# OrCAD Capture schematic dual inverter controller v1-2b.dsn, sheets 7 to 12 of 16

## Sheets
7 Current Sensor XYZ: size B; title: Controller
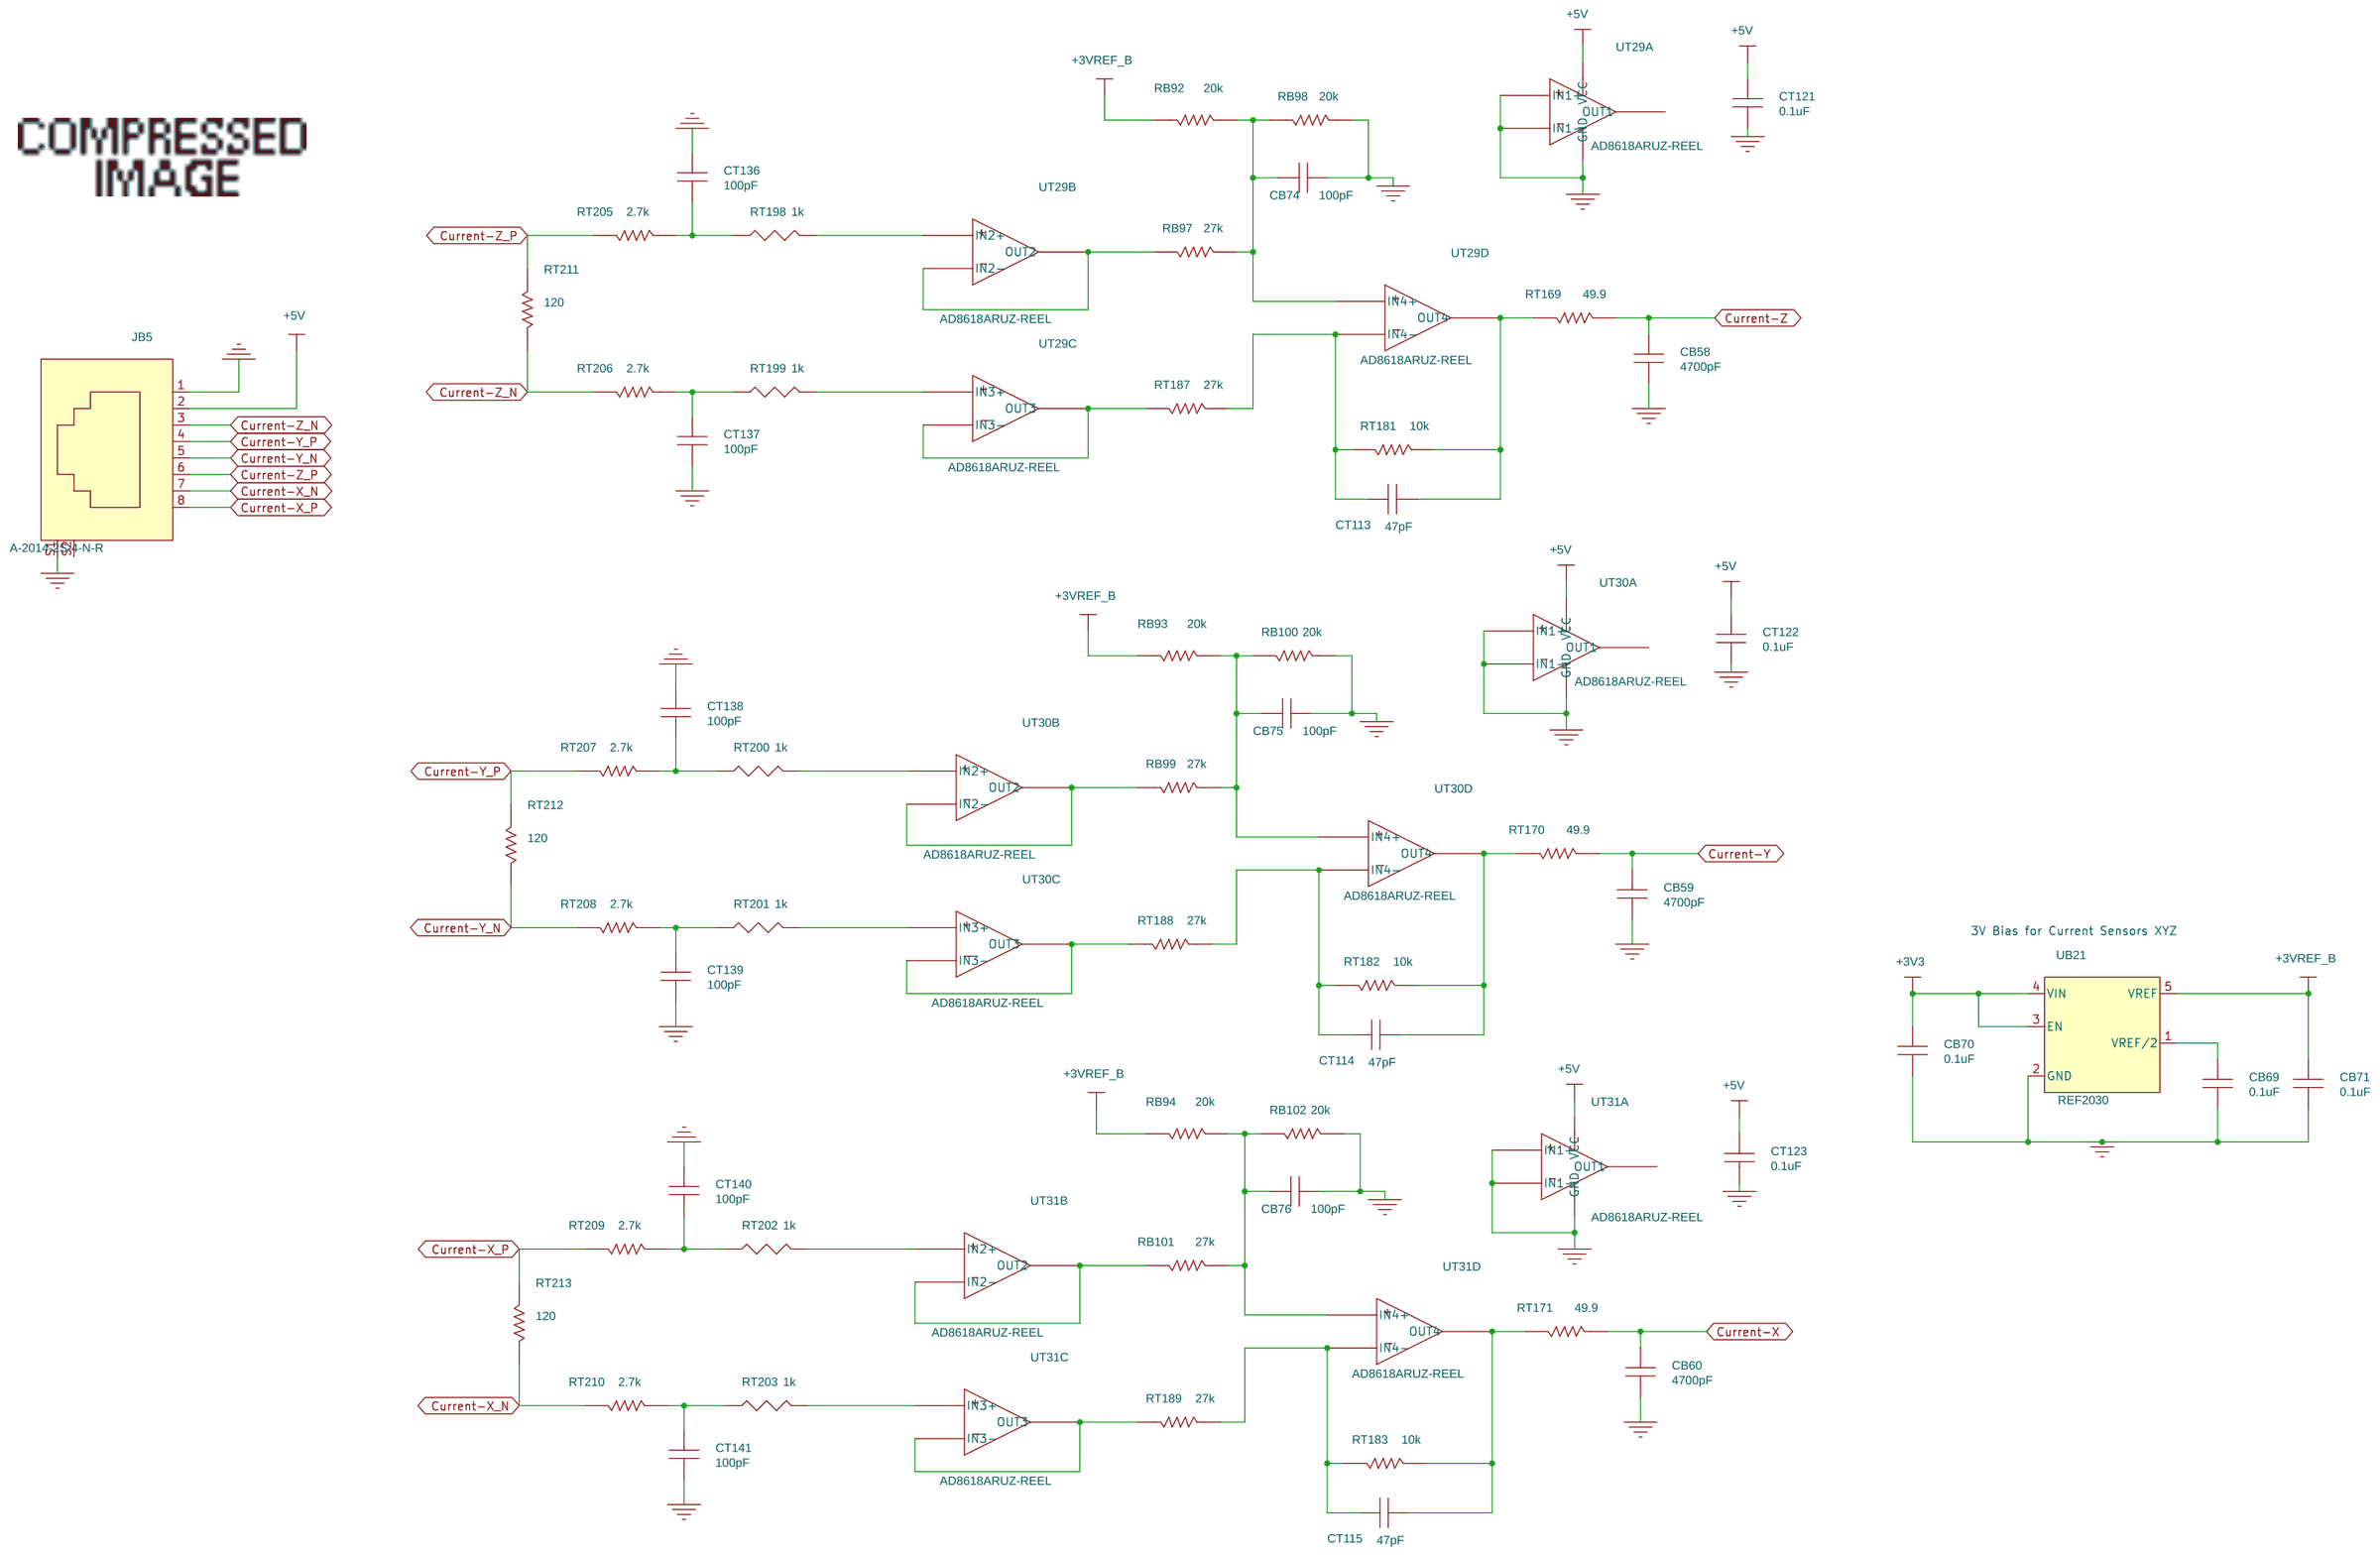
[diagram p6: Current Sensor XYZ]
8 Gate Driver Interface UVW: size A; title: Controller
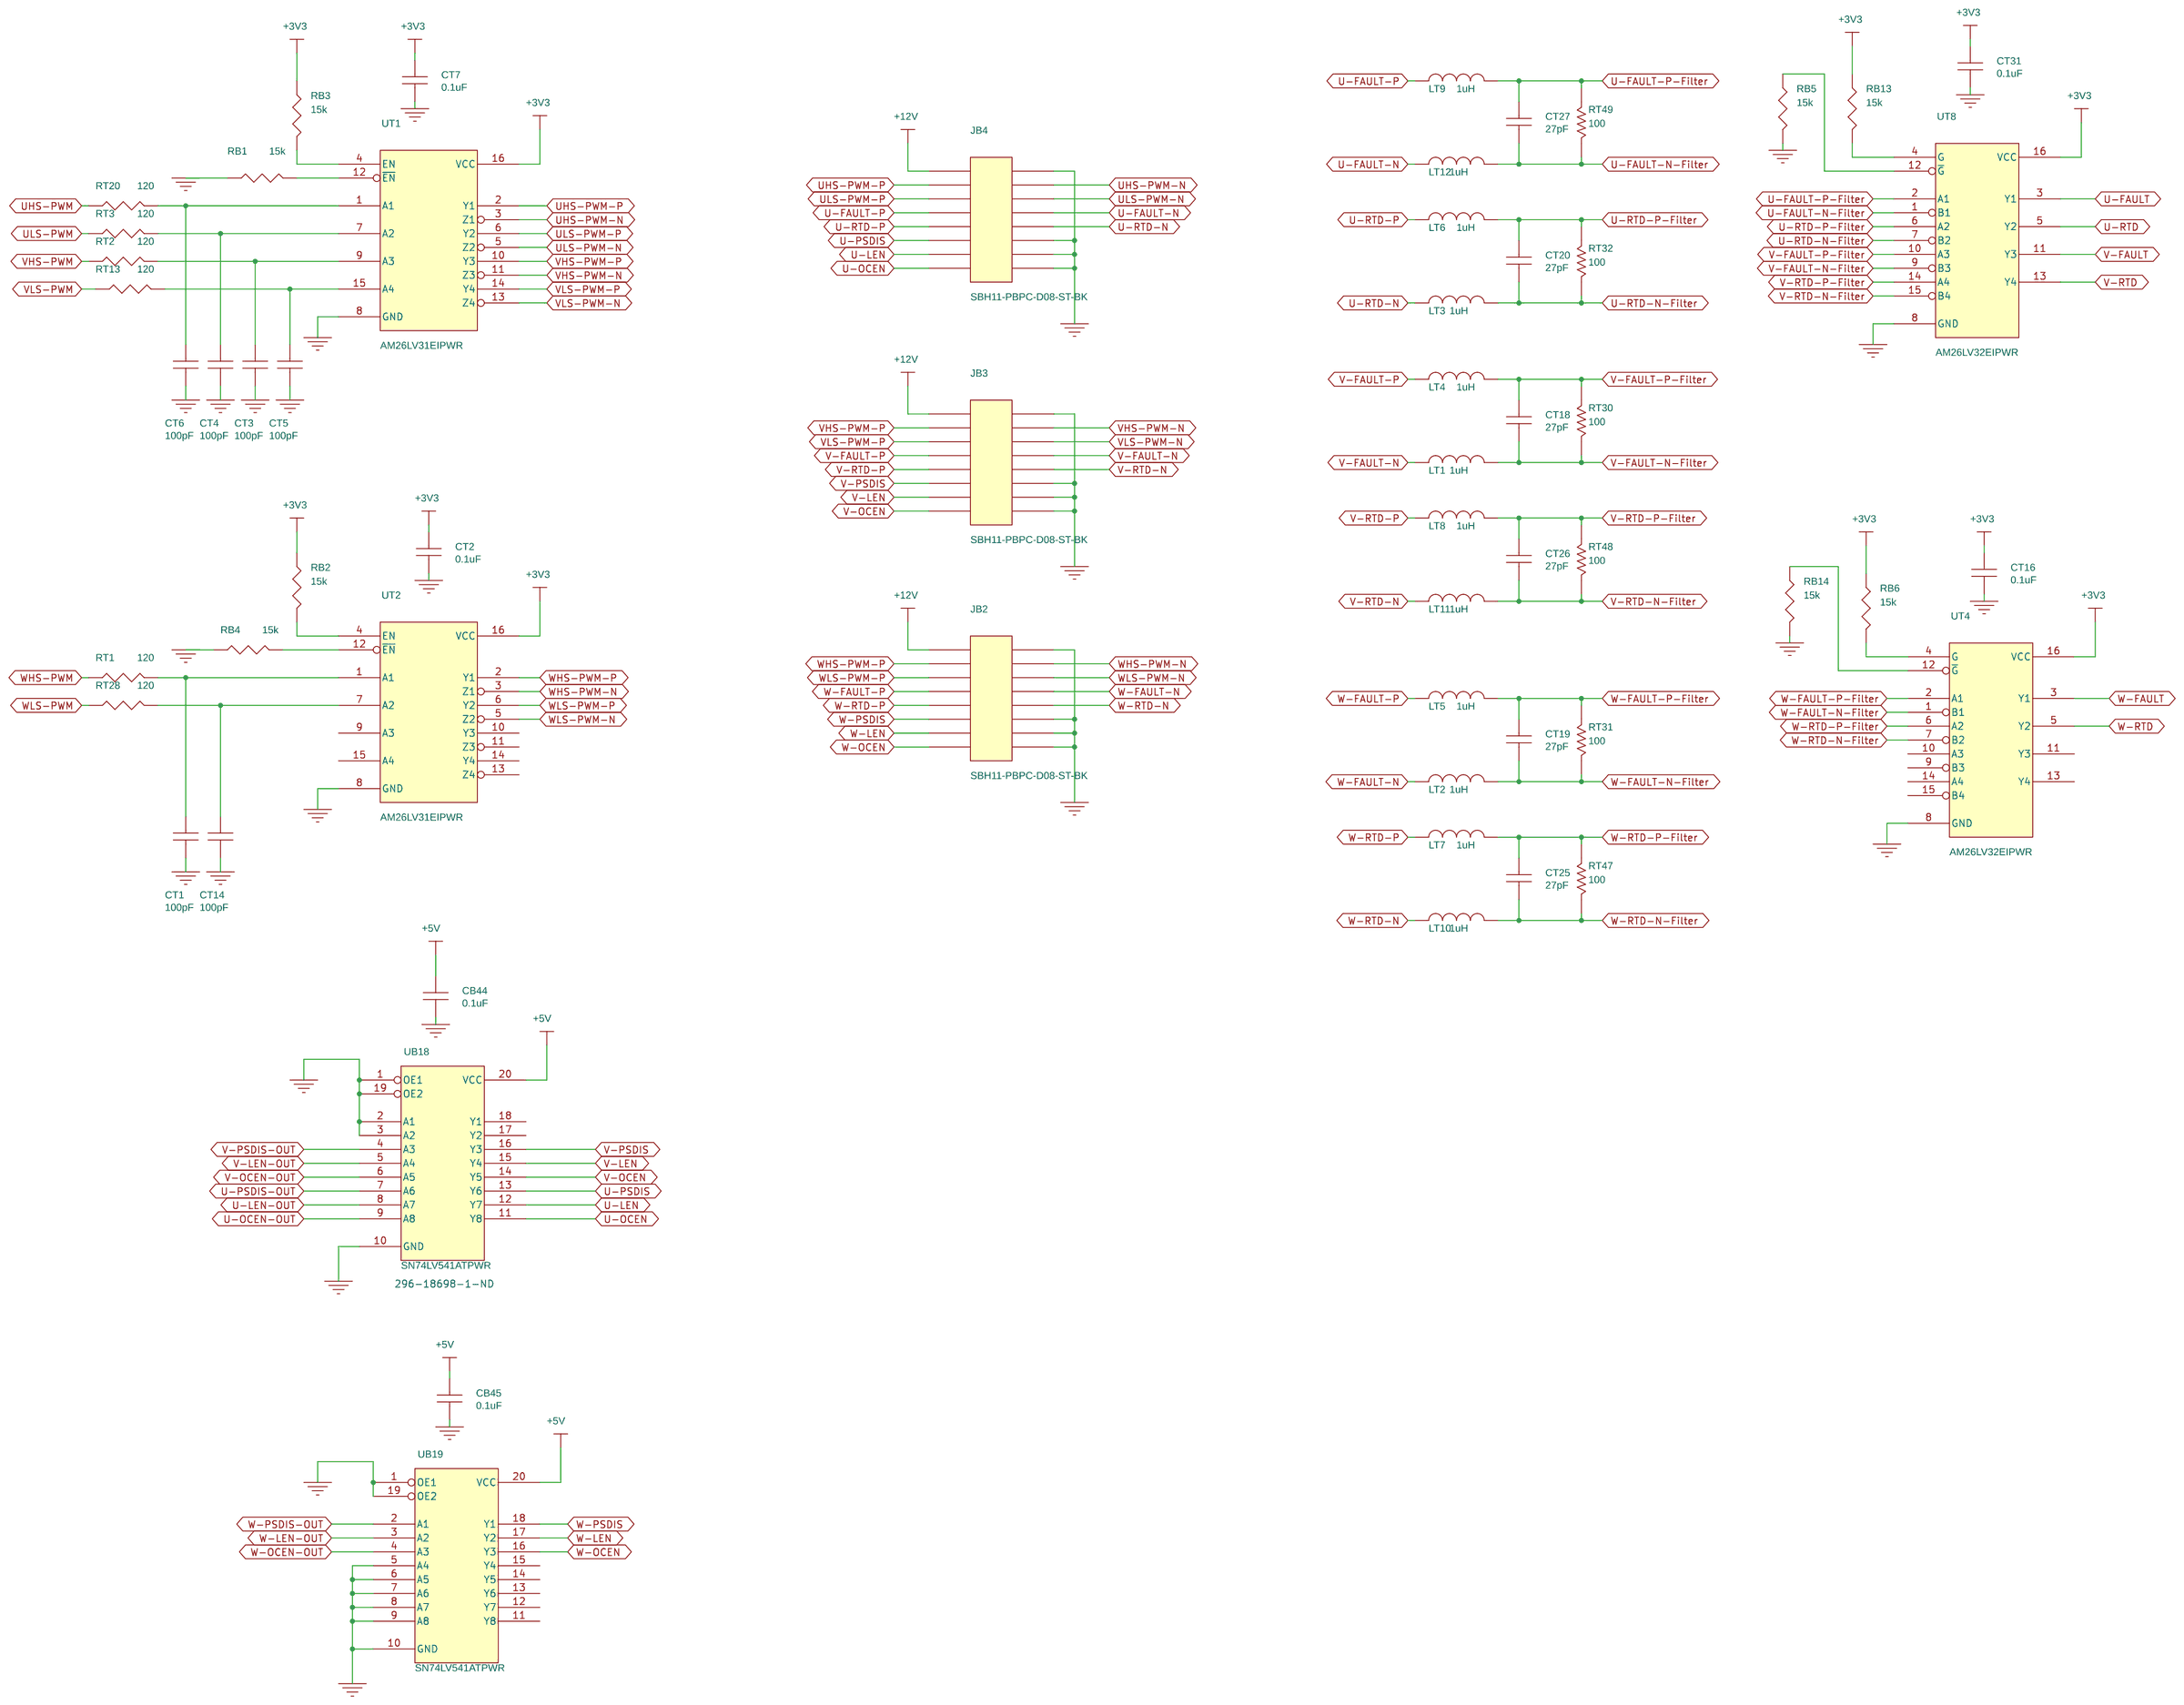
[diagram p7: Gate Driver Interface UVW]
9 Gate Driver Interfave XYZ: size A; title: Controller
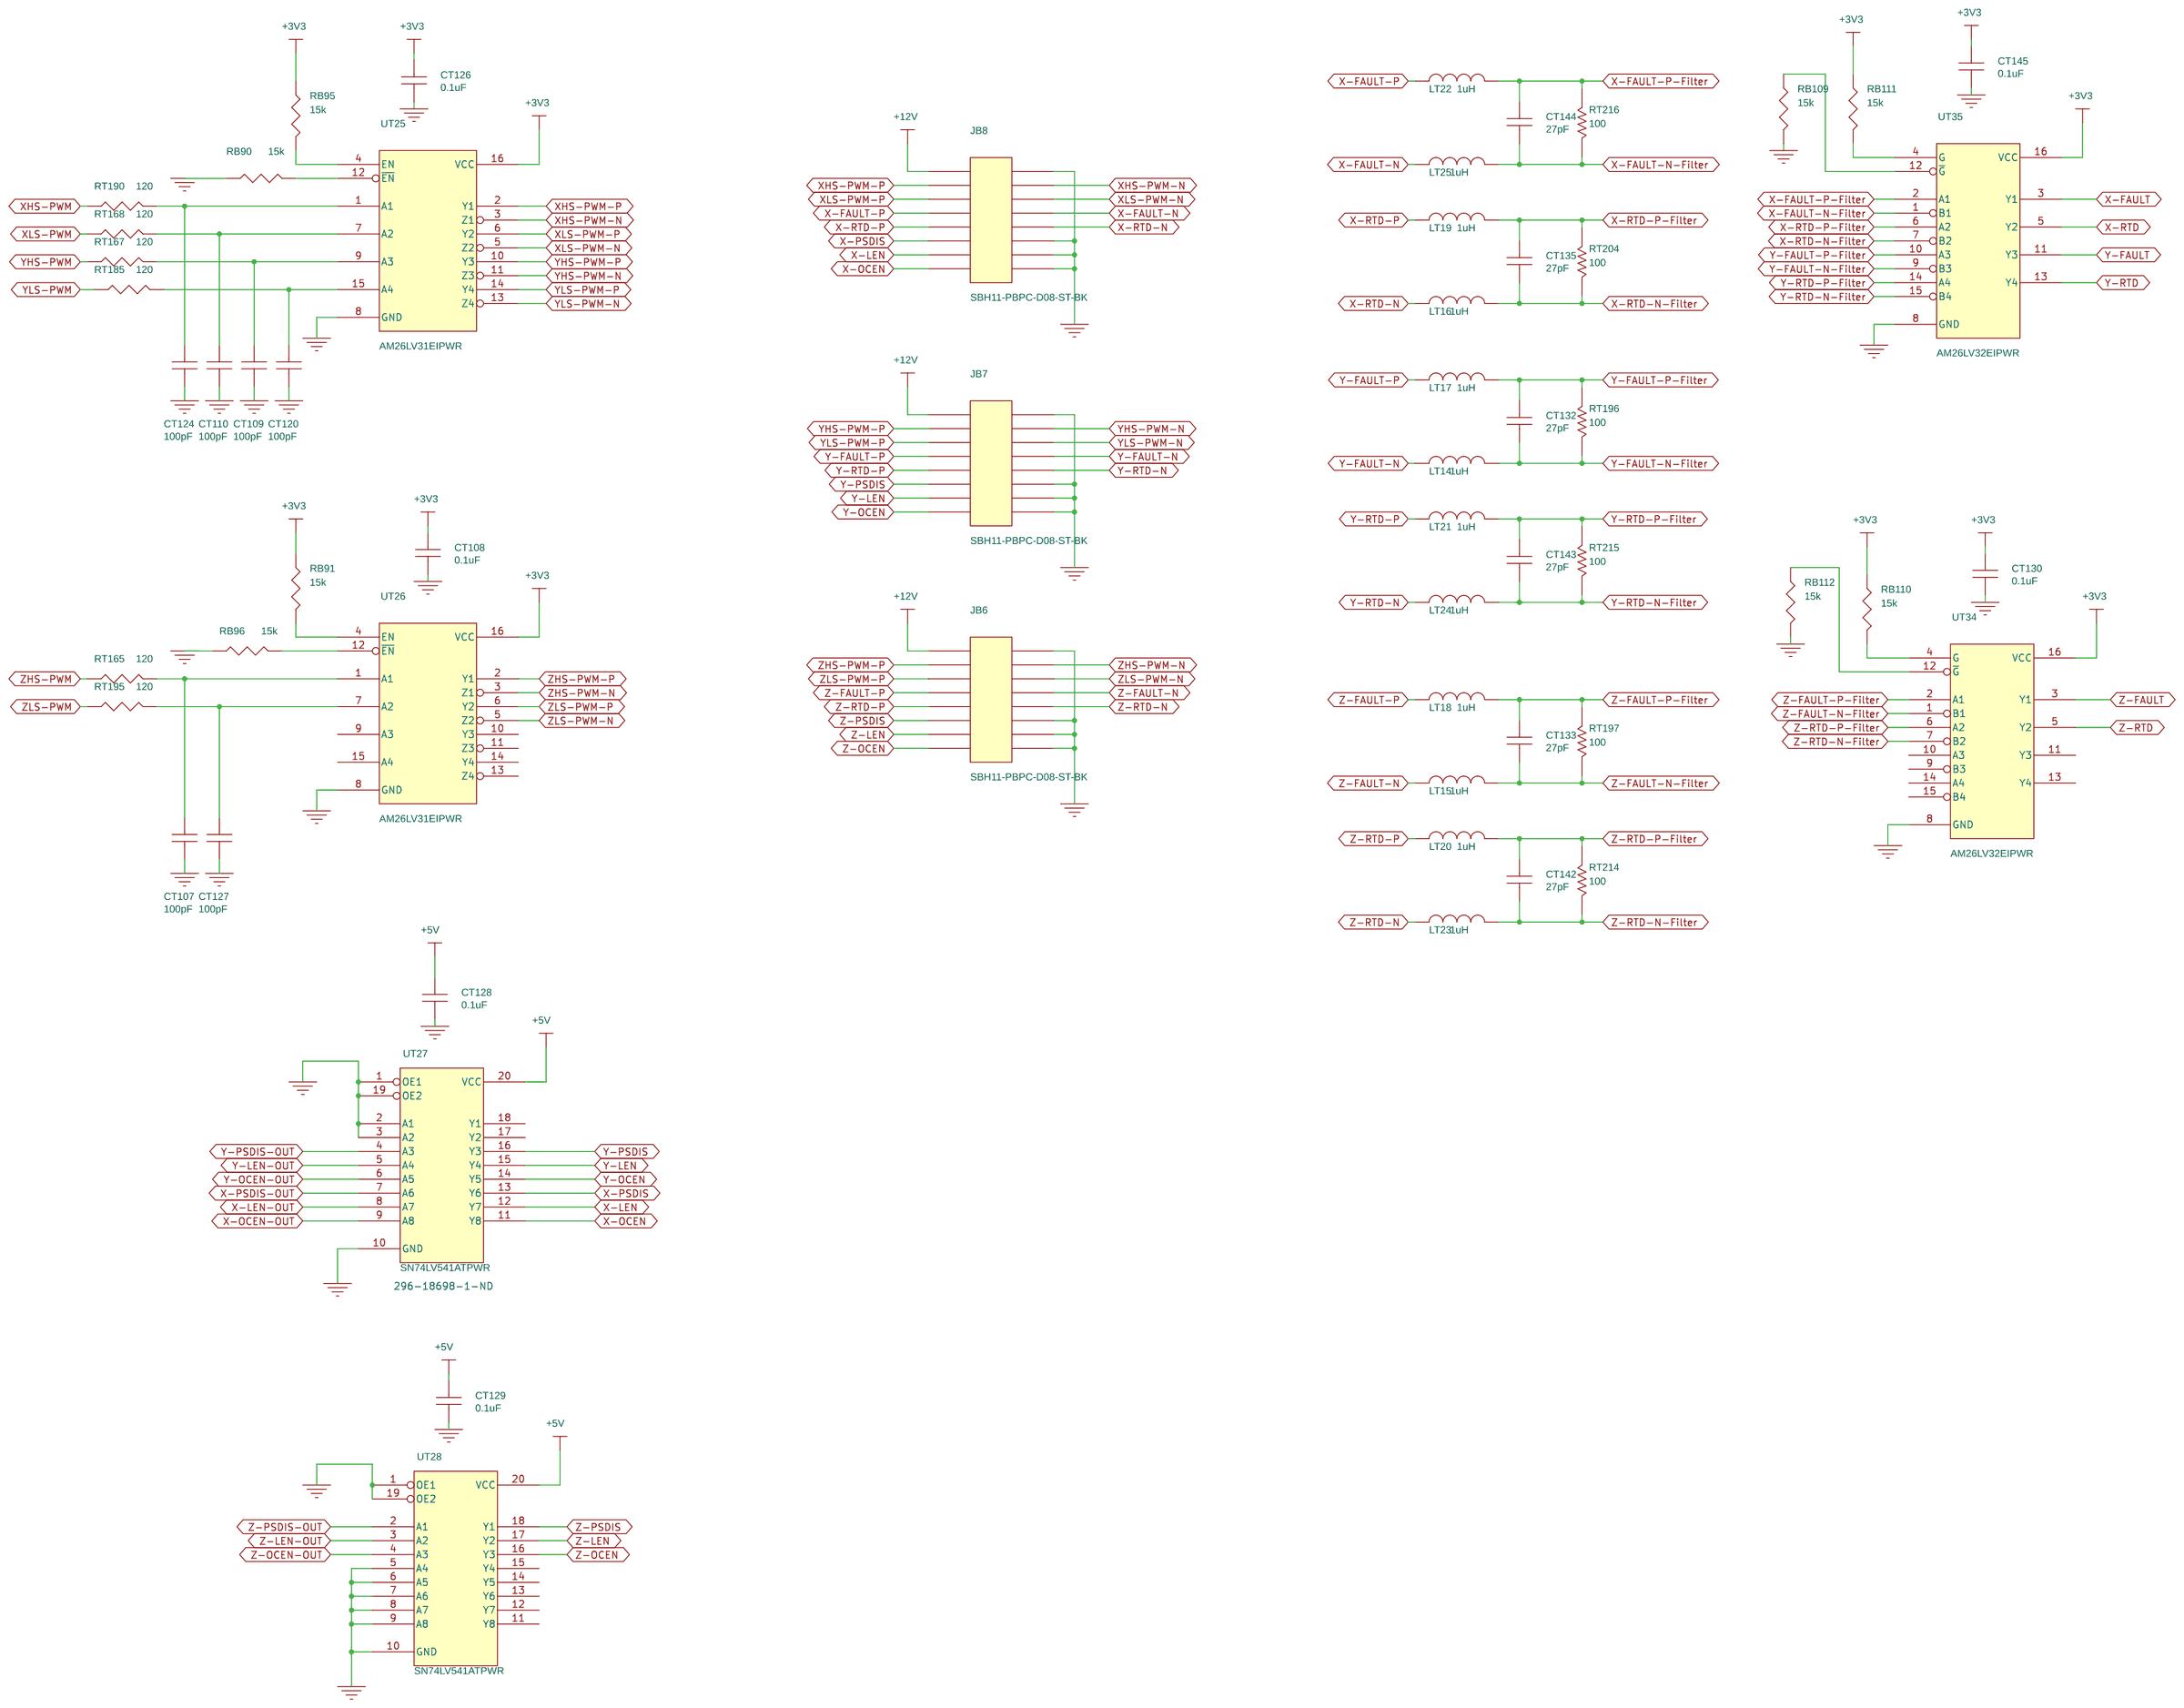
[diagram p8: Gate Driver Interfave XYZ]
10 Power Supply: size A; title: Controller
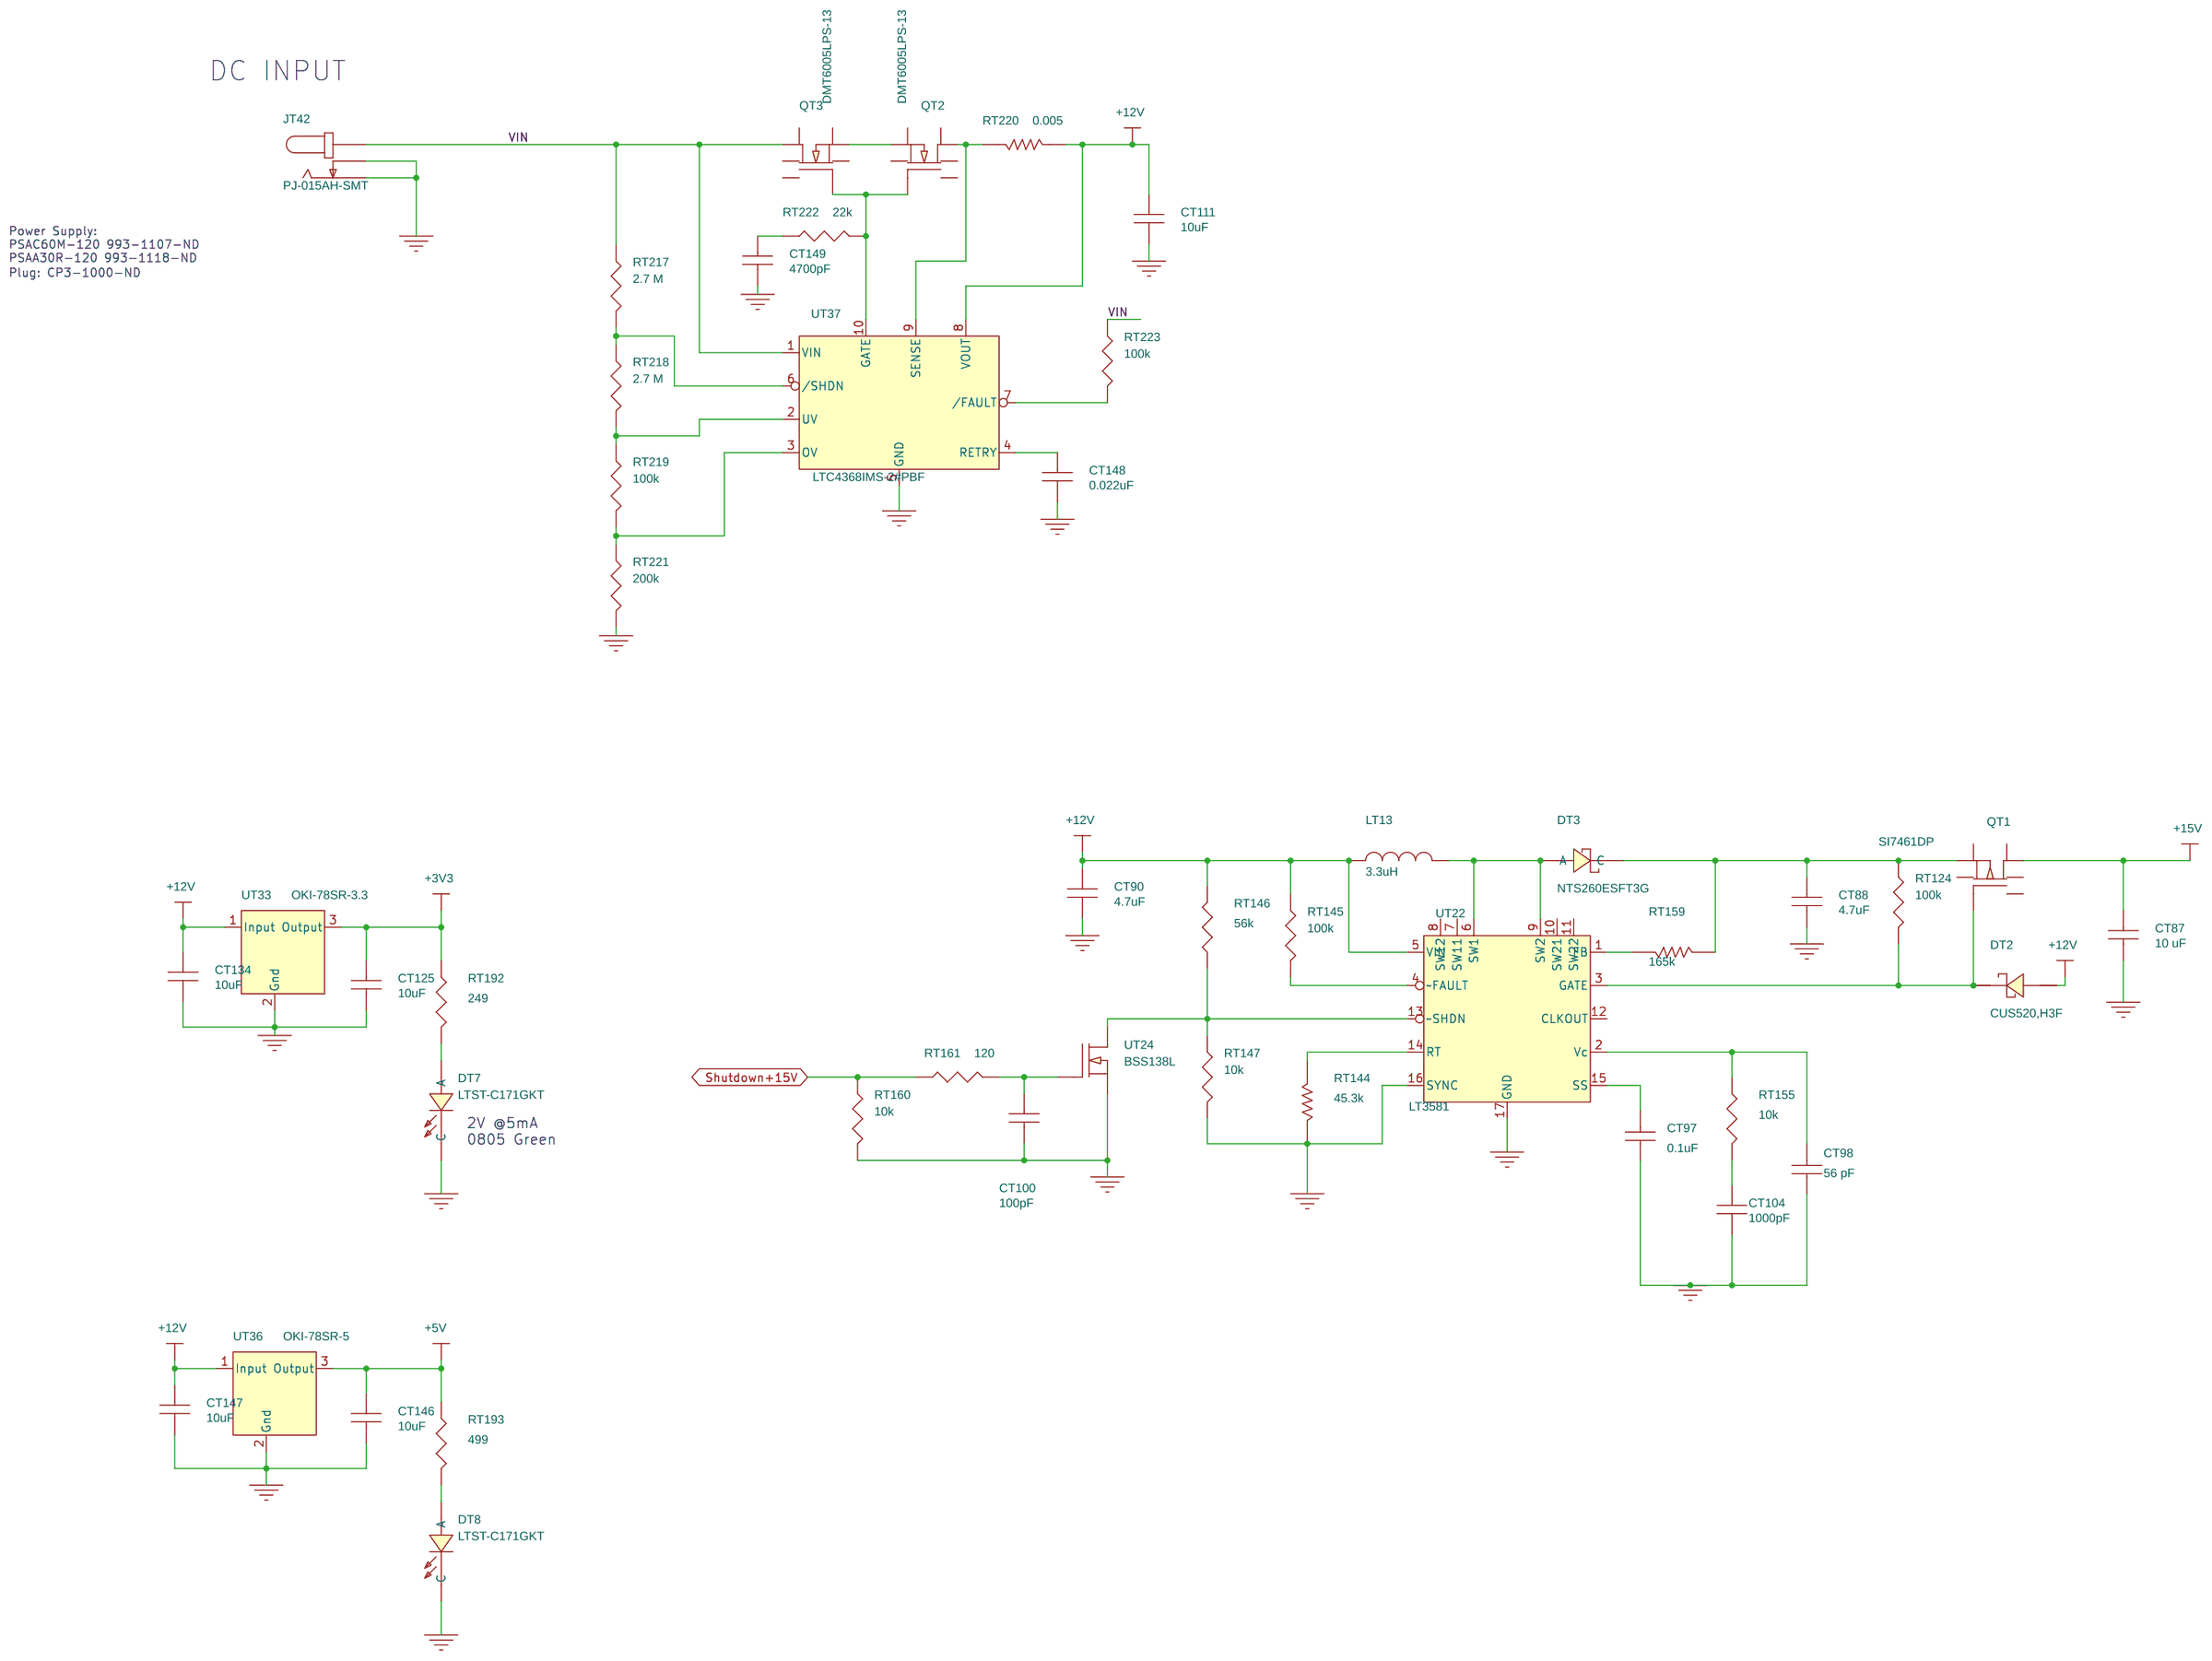
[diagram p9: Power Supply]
11 QEP: size A; title: Controller
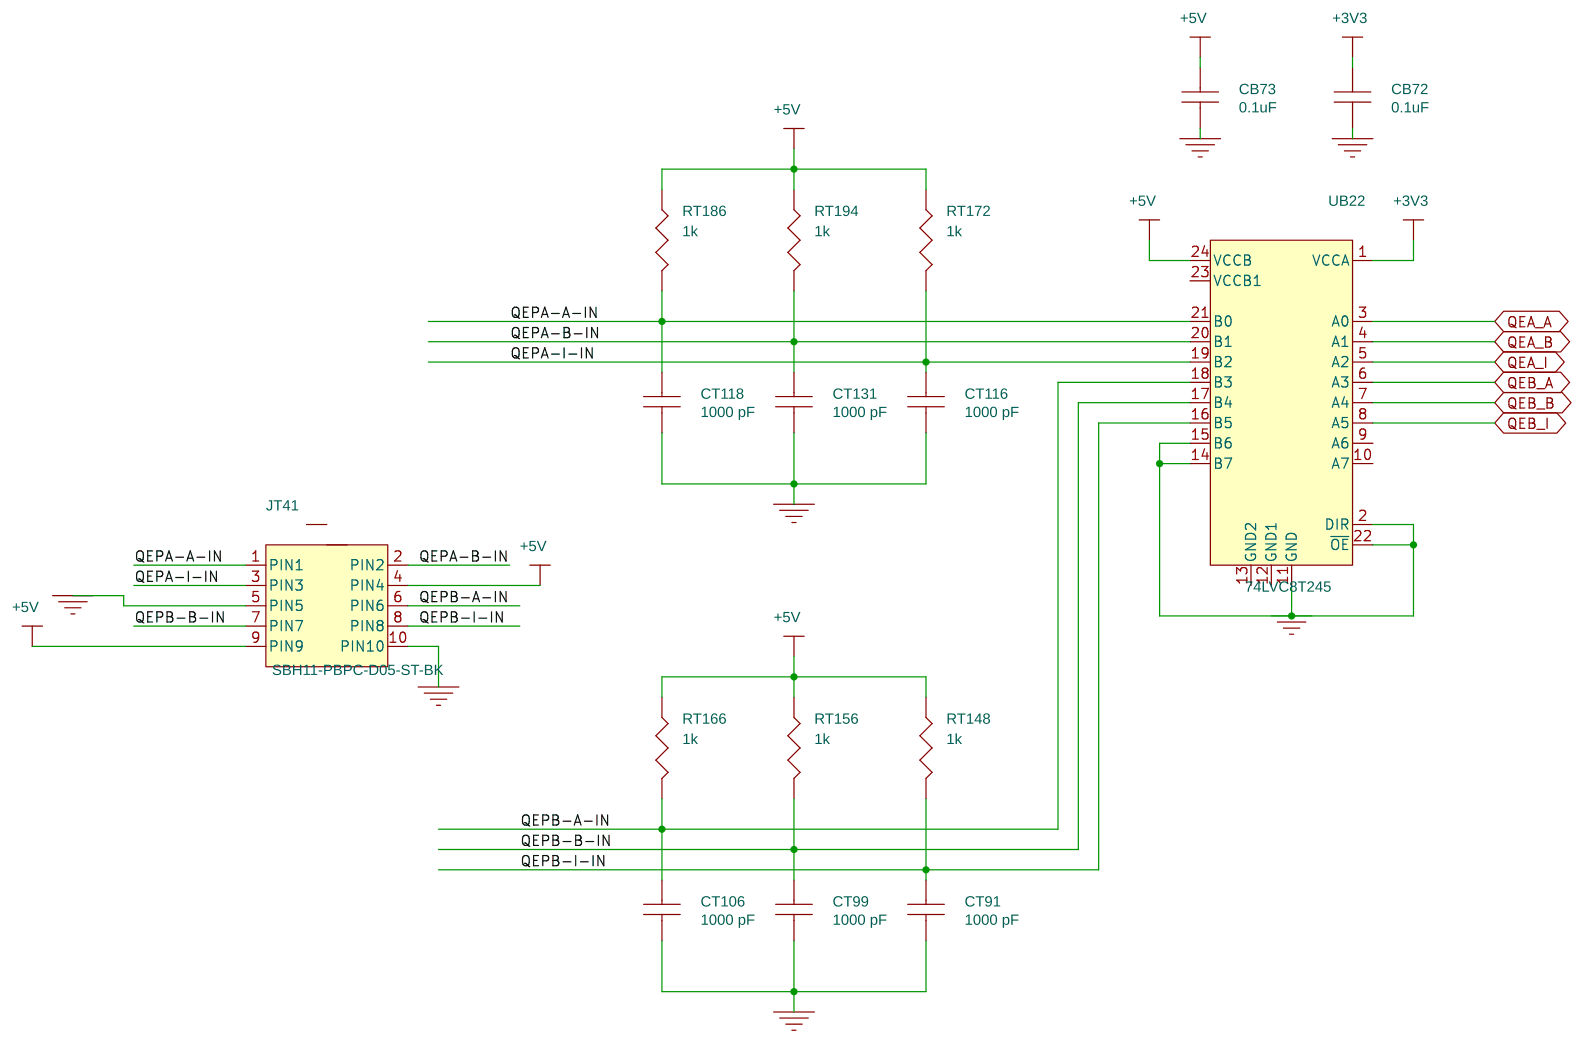
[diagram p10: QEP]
12 Revision History: title: Controller
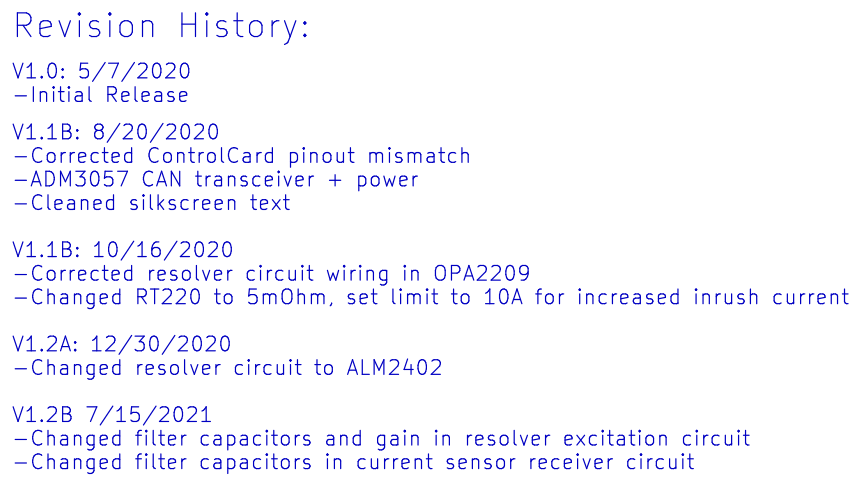
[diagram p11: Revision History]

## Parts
sheet Current Sensor XYZ
CB58  4700pF  [c_0603]
CB59  4700pF  [c_0603]
CB60  4700pF  [c_0603]
CB69  0.1uF  [CAPC1608X87N]
CB70  0.1uF  [CAPC1608X87N]
CB71  0.1uF  [CAPC1608X87N]
CB74  100pF  [CAPC1608X90N]
CB75  100pF  [CAPC1608X90N]
CB76  100pF  [CAPC1608X90N]
CT113  47pF  [CAPC1608X87N]
CT114  47pF  [CAPC1608X87N]
CT115  47pF  [CAPC1608X87N]
CT121  0.1uF  [CAPC1608X87N]
CT122  0.1uF  [CAPC1608X87N]
CT123  0.1uF  [CAPC1608X87N]
CT136  100pF  [CAPC1608X90N]
CT137  100pF  [CAPC1608X90N]
CT138  100pF  [CAPC1608X90N]
CT139  100pF  [CAPC1608X90N]
CT140  100pF  [CAPC1608X90N]
CT141  100pF  [CAPC1608X90N]
JB5  A-2014-2S-4-N-R  [RJ45_VERT_SHIELD_CON]
RB92  20k  [RESC1608X55N]
RB93  20k  [RESC1608X55N]
RB94  20k  [RESC1608X55N]
RB97  27k  [RESC1608X55N]
RB98  20k  [RESC1608X55N]
RB99  27k  [RESC1608X55N]
RB100  20k  [RESC1608X55N]
RB101  27k  [RESC1608X55N]
RB102  20k  [RESC1608X55N]
RT169  49.9  [RESC1608X55N]
RT170  49.9  [RESC1608X55N]
RT171  49.9  [RESC1608X55N]
RT181  10k  [RESC1608X55N]
RT182  10k  [RESC1608X55N]
RT183  10k  [RESC1608X55N]
RT187  27k  [RESC1608X55N]
RT188  27k  [RESC1608X55N]
RT189  27k  [RESC1608X55N]
RT198  1k  [RESC1608X55N]
RT199  1k  [RESC1608X55N]
RT200  1k  [RESC1608X55N]
RT201  1k  [RESC1608X55N]
RT202  1k  [RESC1608X55N]
RT203  1k  [RESC1608X55N]
RT205  2.7k  [RESC1608X55N]
RT206  2.7k  [RESC1608X55N]
RT207  2.7k  [RESC1608X55N]
RT208  2.7k  [RESC1608X55N]
RT209  2.7k  [RESC1608X55N]
RT210  2.7k  [RESC1608X55N]
RT211  120  [RESC1608X55N]
RT212  120  [RESC1608X55N]
RT213  120  [RESC1608X55N]
UB21  REF2030  [SOT23-5_0_95X2_70P_H1_45]
UT29  AD8618ARUZ-REEL  [TSSOP-14]  (sections A,B,C,D)
UT30  AD8618ARUZ-REEL  [TSSOP-14]  (sections A,B,C,D)
UT31  AD8618ARUZ-REEL  [TSSOP-14]  (sections A,B,C,D)
sheet Gate Driver Interface UVW
CB44  0.1uF  [CAPC1608X87N]
CB45  0.1uF  [CAPC1608X87N]
CT1  100pF  [CAPC1608X90N]
CT2  0.1uF  [CAPC1608X87N]
CT3  100pF  [CAPC1608X90N]
CT4  100pF  [CAPC1608X90N]
CT5  100pF  [CAPC1608X90N]
CT6  100pF  [CAPC1608X90N]
CT7  0.1uF  [CAPC1608X87N]
CT14  100pF  [CAPC1608X90N]
CT16  0.1uF  [CAPC1608X87N]
CT18  27pF  [CAPC1608X90N]
CT19  27pF  [CAPC1608X90N]
CT20  27pF  [CAPC1608X90N]
CT25  27pF  [CAPC1608X90N]
CT26  27pF  [CAPC1608X90N]
CT27  27pF  [CAPC1608X90N]
CT31  0.1uF  [CAPC1608X87N]
JB2  SBH11-PBPC-D08-ST-BK  [CON_2x8_shrouded_corrected]
JB3  SBH11-PBPC-D08-ST-BK  [CON_2x8_shrouded_corrected]
JB4  SBH11-PBPC-D08-ST-BK  [CON_2x8_shrouded_corrected]
LT1  1uH  [l_0805]
LT2  1uH  [l_0805]
LT3  1uH  [l_0805]
LT4  1uH  [l_0805]
LT5  1uH  [l_0805]
LT6  1uH  [l_0805]
LT7  1uH  [l_0805]
LT8  1uH  [l_0805]
LT9  1uH  [l_0805]
LT10  1uH  [l_0805]
LT11  1uH  [l_0805]
LT12  1uH  [l_0805]
RB1  15k  [RESC1608X55N]
RB2  15k  [RESC1608X55N]
RB3  15k  [RESC1608X55N]
RB4  15k  [RESC1608X55N]
RB5  15k  [RESC1608X55N]
RB6  15k  [RESC1608X55N]
RB13  15k  [RESC1608X55N]
RB14  15k  [RESC1608X55N]
RT1  120  [RESC1608X55N]
RT2  120  [RESC1608X55N]
RT3  120  [RESC1608X55N]
RT13  120  [RESC1608X55N]
RT20  120  [RESC1608X55N]
RT28  120  [RESC1608X55N]
RT30  100  [RESC1608X55N]
RT31  100  [RESC1608X55N]
RT32  100  [RESC1608X55N]
RT47  100  [RESC1608X55N]
RT48  100  [RESC1608X55N]
RT49  100  [RESC1608X55N]
UB18  SN74LV541ATPWR  [SOP65P640X120-20AN]
UB19  SN74LV541ATPWR  [SOP65P640X120-20AN]
UT1  AM26LV31EIPWR  [TSSOP-16P_P65MM]
UT2  AM26LV31EIPWR  [TSSOP-16P_P65MM]
UT4  AM26LV32EIPWR  [TSSOP-16P_P65MM]
UT8  AM26LV32EIPWR  [TSSOP-16P_P65MM]
sheet Gate Driver Interfave XYZ
CT107  100pF  [CAPC1608X90N]
CT108  0.1uF  [CAPC1608X87N]
CT109  100pF  [CAPC1608X90N]
CT110  100pF  [CAPC1608X90N]
CT120  100pF  [CAPC1608X90N]
CT124  100pF  [CAPC1608X90N]
CT126  0.1uF  [CAPC1608X87N]
CT127  100pF  [CAPC1608X90N]
CT128  0.1uF  [CAPC1608X87N]
CT129  0.1uF  [CAPC1608X87N]
CT130  0.1uF  [CAPC1608X87N]
CT132  27pF  [CAPC1608X90N]
CT133  27pF  [CAPC1608X90N]
CT135  27pF  [CAPC1608X90N]
CT142  27pF  [CAPC1608X90N]
CT143  27pF  [CAPC1608X90N]
CT144  27pF  [CAPC1608X90N]
CT145  0.1uF  [CAPC1608X87N]
JB6  SBH11-PBPC-D08-ST-BK  [CON_2x8_shrouded_corrected]
JB7  SBH11-PBPC-D08-ST-BK  [CON_2x8_shrouded_corrected]
JB8  SBH11-PBPC-D08-ST-BK  [CON_2x8_shrouded_corrected]
LT14  1uH  [l_0805]
LT15  1uH  [l_0805]
LT16  1uH  [l_0805]
LT17  1uH  [l_0805]
LT18  1uH  [l_0805]
LT19  1uH  [l_0805]
LT20  1uH  [l_0805]
LT21  1uH  [l_0805]
LT22  1uH  [l_0805]
LT23  1uH  [l_0805]
LT24  1uH  [l_0805]
LT25  1uH  [l_0805]
RB90  15k  [RESC1608X55N]
RB91  15k  [RESC1608X55N]
RB95  15k  [RESC1608X55N]
RB96  15k  [RESC1608X55N]
RB109  15k  [RESC1608X55N]
RB110  15k  [RESC1608X55N]
RB111  15k  [RESC1608X55N]
RB112  15k  [RESC1608X55N]
RT165  120  [RESC1608X55N]
RT167  120  [RESC1608X55N]
RT168  120  [RESC1608X55N]
RT185  120  [RESC1608X55N]
RT190  120  [RESC1608X55N]
RT195  120  [RESC1608X55N]
RT196  100  [RESC1608X55N]
RT197  100  [RESC1608X55N]
RT204  100  [RESC1608X55N]
RT214  100  [RESC1608X55N]
RT215  100  [RESC1608X55N]
RT216  100  [RESC1608X55N]
UT25  AM26LV31EIPWR  [TSSOP-16P_P65MM]
UT26  AM26LV31EIPWR  [TSSOP-16P_P65MM]
UT27  SN74LV541ATPWR  [SOP65P640X120-20AN]
UT28  SN74LV541ATPWR  [SOP65P640X120-20AN]
UT34  AM26LV32EIPWR  [TSSOP-16P_P65MM]
UT35  AM26LV32EIPWR  [TSSOP-16P_P65MM]
sheet Power Supply
CT87  10 uF  [CAPC3216X180N]
CT88  4.7uF  [CAPc3216X180N]
CT90  4.7uF  [CAPc3216X180N]
CT97  0.1uF  [CAPC1608X90N]
CT98  56 pF  [CAPC1608X90N]
CT100  100pF  [CAPC1608X90N]
CT104  1000pF  [CAPC1608X90N]
CT111  10uF  [CAPC2012X135N]
CT125  10uF  [CAPC2012X135N]
CT134  10uF  [CAPC2012X135N]
CT146  10uF  [CAPC2012X135N]
CT147  10uF  [CAPC2012X135N]
CT148  0.022uF  [CAPC2012X70N]
CT149  4700pF  [CAPC1608X90N]
DT2  CUS520,H3F  [SOD-323-AC]
DT3  NTS260ESFT3G  [SOD-123F-AC]
DT7  LTST-C171GKT  [D_0805]
DT8  LTST-C171GKT  [D_0805]
JT42  PJ-015AH-SMT  [CUI_PJ-015AH-SMT-TR]
LT13  3.3uH  [IND-5040]
QT1  SI7461DP  [POWER-SO8]
QT2  DMT6005LPS-13  [POWER-SO8]
QT3  DMT6005LPS-13  [POWER-SO8]
RT124  100k  [RESC1608X55N]
RT144  45.3k  [RESC1608X55N]
RT145  100k  [RESC1608X55N]
RT146  56k  [RESC1608X55N]
RT147  10k  [RESC1608X65N]
RT155  10k  [RESC1608X65N]
RT159  165k  [RESC1608X55N]
RT160  10k  [RESC1608X65N]
RT161  120  [RESC1608X55N]
RT192  249  [RESC2012X60N]
RT193  499  [RESC2012X60N]
RT217  2.7 M  [RESC1608X55N]
RT218  2.7 M  [RESC1608X55N]
RT219  100k  [RESC1608X55N]
RT220  0.005  [RESC6432X70N]
RT221  200k  [RESC1608X55N]
RT222  22k  [RESC1608X55N]
RT223  100k  [RESC1608X55N]
UT22  LT3581  [MSOP-16-EP]
UT24  BSS138L  [SOT_23_3]
UT33  OKI-78SR-3.3  [oki-78sr-H]
UT36  OKI-78SR-5  [oki-78sr-H]
UT37  LTC4368IMS-2#PBF  [MSOP_10]
sheet QEP
CB72  0.1uF  [CAPC1608X87N]
CB73  0.1uF  [CAPC1608X87N]
CT91  1000 pF  [CAPC1608X90N]
CT99  1000 pF  [CAPC1608X90N]
CT106  1000 pF  [CAPC1608X90N]
CT116  1000 pF  [CAPC1608X90N]
CT118  1000 pF  [CAPC1608X90N]
CT131  1000 pF  [CAPC1608X90N]
JT41  SBH11-PBPC-D05-ST-BK  [CON_2x5_shrouded]
RT148  1k  [RESC1608X55N]
RT156  1k  [RESC1608X55N]
RT166  1k  [RESC1608X55N]
RT172  1k  [RESC1608X55N]
RT186  1k  [RESC1608X55N]
RT194  1k  [RESC1608X55N]
UB22  74LVC8T245  [SOP65P640X120-24N]

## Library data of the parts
CB58-CB60 = CAP: CAP CER 4700PF 25V X7R 0603; CLASS: DISCRETE; Company Part Status: New; Dielectric Type: Capacitors; Manufacturer: Murata Electronics North America; Manufacturer PN: GCM188R71E472KA37D; PART_NUMBER: TMP-889; Package Size: 0603 (1608 Metric); Rated Voltage: 25V; Temperature Coefficient: X7R; Tolerance: 10%
CB44 CB45 CB69-CB73 CT2 CT7 CT16 CT31 CT108 CT121-CT123 CT126 CT128-CT130 CT145 = CAP: CAP CER 0.1UF 25V X7R 0603; CLASS: DISCRETE; Company Part Status: New; Dielectric Type: Capacitors; Manufacturer: Kemet; Manufacturer PN: C0603C104K3RACTU; PART_NUMBER: TMP-847; Package Size: 0603 (1608 Metric); Rated Voltage: 25V; Temperature Coefficient: X7R; Tolerance: 10%
CB74-CB76 CT1 CT3-CT6 CT14 CT100 CT107 CT109 CT110 CT120 CT124 CT127 CT136-CT141 = CAP: CAP CER 100PF 50V 5% NP0 0603; CLASS: DISCRETE; Company Part Status: New; Dielectric Type: Capacitors; Manufacturer: Samsung Electro-Mechanics America, Inc; Manufacturer PN: CL10C101JB8NNNC; PART_NUMBER: TMP-455; Package Size: 0603 (1608 Metric); Rated Voltage: 50V; Temperature Coefficient: C0G, NP0; Tolerance: 5%
CT113-CT115 = CAP: CAP CER 47PF 100V C0G/NP0 0603; CLASS: DISCRETE; Company Part Status: New; Manufacturer: KEMET; Manufacturer PN: C0603C470J1GACTU; PART_NUMBER: TMP-1716; Package Size: 0603 (1608 Metric); Rated Voltage: 100V; Temperature Coefficient: C0G, NP0; Tolerance: 5%
JB5 = ModularJack8P8C-shielded: CONN MOD JACK 8P8C VERT SHIELDED; CLASS: IO; Company Part Status: New; Contact Voltage: 150V; Manufacturer: Assmann WSW Components; PART_NUMBER: TMP-1660
RB92-RB94 RB98 RB100 RB102 = RES: RES SMD 20K OHM 1% 1/10W 0603; CLASS: DISCRETE; Company Part Status: Released; Manufacturer: Yageo; Manufacturer PN: RC0603FR-0720KL; PART_NUMBER: TMP-873; Package Size: 0603 (1608 Metric); Rated Power: 0.1W, 1/10W; Temperature Coefficient: 100ppm/C; Tolerance: 1%
RB97 RB99 RB101 RT187-RT189 = RES: Thick Film Resistors - SMD 0603 Anti-Surge Res. 0.1%, 27Kohm; CLASS: DISCRETE; Company Part Status: New; Manufacturer: Panasonic; Manufacturer PN: ERJ-PB3B2702V; PART_NUMBER: TMP-1751; Rated Power: 200 mW (1/5 W); Temperature Coefficient: 50 PPM / C; Tolerance: 0.1%
RT169-RT171 = RES: RES SMD 49.9 OHM 1% 1/10W 0603; CLASS: DISCRETE; Company Part Status: New; Manufacturer: Panasonic Electronic Components; Manufacturer PN: ERJ-3EKF49R9V; PART_NUMBER: TMP-1252; Package Size: 0603 (1608 Metric); Rated Power: 0.1W, 1/10W; Temperature Coefficient: 100ppm/C; Tolerance: 1%
RT181-RT183 = RES: RES SMD 10K OHM 1% 1/10W 0603; CLASS: DISCRETE; Company Part Status: New; Manufacturer: Panasonic Electronic Components; Manufacturer PN: ERJ-3EKF1002V; PART_NUMBER: TMP-788; Package Size: 0603 (1608 Metric); Rated Power: 0.1W, 1/10W; Temperature Coefficient: 100ppm/C; Tolerance: 1%
RT148 RT156 RT166 RT172 RT186 RT194 RT198-RT203 = R: RES SMD 1K OHM 1% 1/10W 0603; CLASS: DISCRETE; Company Part Status: New; Manufacturer: Panasonic Electronic Components; Manufacturer PN: ERJ-3EKF1001V; PART_NUMBER: TMP-1344; Package Size: 0603 (1608 Metric); Rated Power: 0.1W, 1/10W; Temperature Coefficient: 100ppm/C; Tolerance: 1%
RT205-RT210 = RES: Thick Film Resistors - SMD 0603 Anti-Surge Res. 0.1%, 2.7Kohm; CLASS: DISCRETE; Company Part Status: New; Manufacturer: Panasonic; Manufacturer PN: ERJ-PB3B2701V; PART_NUMBER: TMP-1750; Rated Power: 200 mW (1/5 W); Temperature Coefficient: 50 PPM / C; Tolerance: 0.1%
RT211-RT213 = RES_0: RES SMD 120 OHM 1% 1/10W 0603; CLASS: DISCRETE; Company Part Status: Released; Manufacturer: Yageo; Manufacturer PN: RC0603FR-07120RL; PART_NUMBER: TMP-957; Package Size: 0603 (1608 Metric); Rated Power: 0.1W, 1/10W; Temperature Coefficient: 100ppm/C; Tolerance: 1%
UB21 = REF2030: IC VREF SERIES 1.5V AND 3V 0.05% SOT23-5; CLASS: IC; Company Part Status: New; Manufacturer: Texas Instruments; Manufacturer PN: REF2030AIDDCT; PART_NUMBER: TMP-1708; Package Size: SOT-23-5 Thin, TSOT-23-5; Supply Voltage: 3 - 5.5 V
UT29 = OPAMP_4X_14P: IC OPAMP GP 24MHZ RRO 14TSSOP; CLASS: IC; Company Part Status: New; Manufacturer: Analog Devices Inc.; PART_NUMBER: TMP-1501; Package Size: 14-TSSOP (0.173", 4.40mm Width); PartGroup: CurrentX; Supply Voltage: 2.7 V - 5.5 V, 1.35 V - 2.75 V
UT30 = OPAMP_4X_14P: IC OPAMP GP 24MHZ RRO 14TSSOP; CLASS: IC; Company Part Status: New; Manufacturer: Analog Devices Inc.; PART_NUMBER: TMP-1501; Package Size: 14-TSSOP (0.173", 4.40mm Width); PartGroup: CurrentY; Supply Voltage: 2.7 V - 5.5 V, 1.35 V - 2.75 V
UT31 = OPAMP_4X_14P: IC OPAMP GP 24MHZ RRO 14TSSOP; CLASS: IC; Company Part Status: New; Manufacturer: Analog Devices Inc.; PART_NUMBER: TMP-1501; Package Size: 14-TSSOP (0.173", 4.40mm Width); PartGroup: CurrentZ; Supply Voltage: 2.7 V - 5.5 V, 1.35 V - 2.75 V
CT18-CT20 CT25-CT27 CT132 CT133 CT135 CT142-CT144 = CAP: CAP CER 27PF 50V NP0 0603; CLASS: DISCRETE; Company Part Status: New; Dielectric Type: Capacitors; Manufacturer: Samsung Electro-Mechanics America, Inc.; Manufacturer PN: CL10C270JB8NNNC; PART_NUMBER: TMP-759; Package Size: 0603 (1608 Metric); Rated Voltage: 50V; Temperature Coefficient: C0G, NP0; Tolerance: 5%
JB2-JB4 JB6-JB8 = CON16A_Corrected: CONN HEADER 2.54MM 16POS GOLD; CLASS: IO; Company Part Status: New; Manufacturer: Sullins Connector Solutions; PART_NUMBER: TMP-739
LT1-LT12 LT14-LT25 = INDUCTOR: FIXED IND 1UH 1.15A 60 MOHM SMD; CLASS: DISCRETE; Company Part Status: New; Manufacturer: TDK Corporation; Manufacturer PN: MLZ2012N1R0LT000; PART_NUMBER: TMP-610; Package Size: 0805 (2012 Metric); Tolerance: 20%
RB1-RB6 RB13 RB14 RB90 RB91 RB95 RB96 RB109-RB112 = R: RES SMD 15K OHM 5% 1/10W 0603; CLASS: DISCRETE; Company Part Status: New; Manufacturer: Yageo; Manufacturer PN: RC0603JR-0715KL; PART_NUMBER: TMP-618; Package Size: 0603 (1608 Metric); Rated Power: 0.1W, 1/10W; Temperature Coefficient: 100ppm/C; Tolerance: 5%
RT1-RT3 RT13 RT20 RT28 RT161 RT165 RT167 RT168 RT185 RT190 RT195 = R: RES SMD 120 OHM 5% 1/10W 0603; CLASS: DISCRETE; Company Part Status: New; Manufacturer: Yageo; Manufacturer PN: RC0603JR-07120RL; PART_NUMBER: TMP-619; Package Size: 0603 (1608 Metric); Rated Power: 0.1W, 1/10W; Temperature Coefficient: 100ppm/C; Tolerance: 5%
RT30-RT32 RT47-RT49 RT196 RT197 RT204 RT214-RT216 = RES: RES SMD 100 OHM 1% 1/10W 0603; CLASS: DISCRETE; Company Part Status: New; Manufacturer: Yageo; Manufacturer PN: RC0603FR-07100RL; PART_NUMBER: TMP-865; Package Size: 0603 (1608 Metric); Rated Power: 0.1W, 1/10W; Temperature Coefficient: 100ppm/C; Tolerance: 1%
UB18 UT27 = 74-541_20P: IC BUF NON-INVERT 5.5V 20TSSOP; CLASS: IC; Company Part Status: New; Digikey: 296-18698-1-ND; Manufacturer: Texas Instruments; PART_NUMBER: TMP-1497; Package Size: 20-TSSOP (0.173", 4.40mm Width); Supply Voltage: 4.5 V - 5.5 V
UB19 UT28 = 74-541_20P: IC BUF NON-INVERT 5.5V 20TSSOP; CLASS: IC; Company Part Status: New; Manufacturer: Texas Instruments; PART_NUMBER: TMP-1497; Package Size: 20-TSSOP (0.173", 4.40mm Width); Supply Voltage: 4.5 V - 5.5 V
UT1 UT2 UT25 UT26 = DIFFDRVR_4X_16P: IC DVR DIFF QUAD LV HS 16TSSOP; CLASS: IC; Company Part Status: New; Manufacturer: Texas Instruments; PART_NUMBER: TMP-1494; Package Size: 16-TSSOP (0.173", 4.40mm Width); Supply Voltage: 3 V - 3.6 V
UT4 UT8 UT34 UT35 = DIFFRCVR_4XG_16P: IC RCVR DIFF QUAD LV HS 16TSSOP; CLASS: IC; Company Part Status: New; Manufacturer: Texas Instruments; PART_NUMBER: TMP-1495; Package Size: 16-TSSOP (0.173", 4.40mm Width); Supply Voltage: 3 V - 3.6 V
CT87 = CAP: CAP CER 10UF 25V X7R 1206; CLASS: DISCRETE; Company Part Status: Released; Dielectric Type: Capacitors; Manufacturer: Samsung Electro-Mechanics; Manufacturer PN: CL31B106KAHNNNE; PART_NUMBER: TMP-1386; Package Size: 1206 (3216 Metric); Rated Voltage: 25V; Temperature Coefficient: X7R; Tolerance: 10%
CT88 CT90 = CAP: CAP CER 4.7UF 50V 10% X7R 1206; CLASS: DISCRETE; Dielectric Type: Ceramic; Manufacturer: Taiyo Yuden; Manufacturer PN: UMK316AB7475KL-T; PART_NUMBER: TMP-119; Package Size: 1206 (3216 Metric); Rated Voltage: 50V; Temperature Coefficient: X7R; Tolerance: ±10%
CT97 = CAP: CAP CER 0.1UF 50V X7R 0603; CLASS: DISCRETE; Company Part Status: Released; Dielectric Type: Capacitors; Manufacturer: Yageo; Manufacturer PN: CC0603KRX7R9BB104; PART_NUMBER: TMP-1516; Package Size: 0603 (1608 Metric); Rated Voltage: 50V; Temperature Coefficient: X7R; Tolerance: 10%
CT98 = CAP: CAP CER 56PF 50V C0G/NP0 0603; CLASS: DISCRETE; Company Part Status: Released; Dielectric Type: Capacitors; Manufacturer: Samsung Electro-Mechanics; Manufacturer PN: CL10C560JB8NNNC; PART_NUMBER: TMP-1515; Package Size: 0603 (1608 Metric); Rated Voltage: 50V; Temperature Coefficient: C0G, NP0; Tolerance: 5%
CT104 = CAP: CAP CER 1000PF 50V X7R 0603; CLASS: DISCRETE; Dielectric Type: Capacitors; Manufacturer: TDK Corporation; Manufacturer PN: CGA3E2X7R1H102K080AA; PART_NUMBER: TMP-887; Package Size: 0603 (1608 Metric); Temperature Coefficient: X7R; Tolerance: 10%
CT111 CT125 CT134 CT146 CT147 = CAP: CAP CER 10UF 25V X7S 0805; CLASS: DISCRETE; Company Part Status: New; Dielectric Type: Capacitors; Manufacturer: Murata Electronics North America; Manufacturer PN: GRM21BC71E106KE11L; PART_NUMBER: TMP-1080; Package Size: 0805 (2012 Metric); Rated Voltage: 25V; Temperature Coefficient: X7S; Tolerance: 10%
CT148 = CAP: CAP CER 0.022UF 50V X7R 0805; CLASS: DISCRETE; Company Part Status: New; Dielectric Type: Ceramic; Manufacturer: Yageo; Manufacturer PN: CC0805KRX7R9BB223; PART_NUMBER: TMP-667; Package Size: 0805 (2012 Metric); Rated Voltage: 50V; Temperature Coefficient: X7R; Tolerance: 10%
CT149 = CAP: CAP CER 4700PF 25V X7R 0603; CLASS: DISCRETE; Dielectric Type: Capacitors; Manufacturer: Murata Electronics North America; Manufacturer PN: GCM188R71E472KA37D; PART_NUMBER: TMP-889; Package Size: 0603 (1608 Metric); Temperature Coefficient: X7R; Tolerance: 10%
DT2 = DIODE_SCHOTTKY_C2_A1_0: DIODE SCHOTTKY 30V 200MA; CLASS: DISCRETE; Company Part Status: Released; Manufacturer: Toshiba Semiconductor and Storage; PART_NUMBER: TMP-880; Package Size: SC-76, SOD-323; Rated Voltage: 280mV @ 10mA
DT3 = DIODE_SCHOTTKY_0: DIODE SCHOTTKY 60V 2A SOD123FL; CLASS: DISCRETE; Company Part Status: New; Manufacturer: ON Semiconductor; PART_NUMBER: TMP-1369; Package Size: SOD-123F; Rated Voltage: 60 V
DT7 DT8 = LED_0: LED GREEN CLEAR 0805 SMD; CLASS: DISCRETE; Company Part Status: Released; Manufacturer: Lite-On Inc.; PART_NUMBER: TMP-1003; Package Size: 0805 (2012 Metric)
JT42 = PJ-015AH-SMT-TR: CONN PWR JACK 2X5.5MM SOLDER; CLASS: IO; Company Part Status: New; Contact Voltage: 24V; Manufacturer: CUI Devices; PART_NUMBER: TMP-1671
LT13 = IND: FIXED IND 3.3UH 3.3A 27 MOHM SMD; CLASS: DISCRETE; Company Part Status: New; Manufacturer: Taiyo Yuden; Manufacturer PN: NRS5040T3R3NMGJ; PART_NUMBER: TMP-1594; Package Size: Nonstandard; Tolerance: 30%
QT1 = MOSFET_P_PSO8: MOSFET P-CH 60V 8.6A PPAK SO-8; CLASS: DISCRETE; Company Part Status: New; Manufacturer: Vishay Siliconix; Manufacturer PN: SI7461DP-T1-E3; PART_NUMBER: TMP-1595; Package Size: PowerPAK® SO-8; Polarity: P-Channel; Rated Power: 1.9W (Ta)
QT2 QT3 = MOSFET_N_PSO8: MOSFET N-CHA 60V 17.9A POWERDI; CLASS: DISCRETE; Company Part Status: New; Manufacturer: Diodes Incorporated; PART_NUMBER: TMP-1530; Package Size: 8-PowerTDFN; Polarity: N-Channel; Rated Power: 2.6 W
RT124 RT145 RT219 RT223 = R: RES SMD 100K OHM 1% 1/10W 0603; CLASS: DISCRETE; Company Part Status: New; Manufacturer: Rohm Semiconductor; Manufacturer PN: MCR03ERTF1003; PART_NUMBER: TMP-382; Package Size: 0603 (1608 Metric); Rated Power: 0.1W, 1/10W; Temperature Coefficient: 100ppm/C; Tolerance: 1%
RT144 = RES: RES 45.3K OHM 1% 1/10W 0603; CLASS: DISCRETE; Company Part Status: New; Manufacturer: Stackpole Electronics Inc; Manufacturer PN: RMCF0603FT45K3; PART_NUMBER: TMP-1597; Package Size: 0603 (1608 Metric); Rated Power: 0.1W, 1/10W; Temperature Coefficient: 100ppm/C; Tolerance: 1%
RT146 = R: RES SMD 56K OHM 1% 1/10W 0603; CLASS: DISCRETE; Company Part Status: New; Manufacturer: Yageo; Manufacturer PN: RC0603FR-0756KL; PART_NUMBER: TMP-614; Package Size: 0603 (1608 Metric); Rated Power: 0.1W, 1/10W; Temperature Coefficient: 100ppm/C; Tolerance: 1%
RT147 RT155 RT160 = R: RES SMD 10K OHM 1% 1/10W 0603; CLASS: DISCRETE; Company Part Status: New; Manufacturer: Rohm Semiconductor; Manufacturer PN: MCR03ERTF1002; PART_NUMBER: TMP-380; Package Size: 0603 (1608 Metric); Rated Power: 0.1W, 1/10W; Temperature Coefficient: 100ppm/C; Tolerance: 1%
RT159 = RES: RES SMD 165K OHM 0.1% 1/10W 0603; CLASS: DISCRETE; Company Part Status: New; Manufacturer: Panasonic Electronic Components; Manufacturer PN: ERA-3AEB1653V; PART_NUMBER: TMP-1598; Package Size: 0603 (1608 Metric); Rated Power: 0.1W, 1/10W; Temperature Coefficient: 25ppm/C; Tolerance: 0.1%
RT192 = R: RES SMD 249 OHM 1% 1/8W 0805; CLASS: DISCRETE; Company Part Status: New; Manufacturer: Rohm Semiconductor; Manufacturer PN: MCR10ERTF2490; PART_NUMBER: TMP-488; Package Size: 0805 (2012 Metric); Rated Power: 0.125W, 1/8W; Temperature Coefficient: 100ppm/C; Tolerance: 1%
RT193 = R: RES SMD 499 OHM 1% 1/8W 0805; CLASS: DISCRETE; Company Part Status: New; Manufacturer: Rohm Semiconductor; Manufacturer PN: MCR10ERTF4990; PART_NUMBER: TMP-897; Package Size: 0805 (2012 Metric); Rated Power: 0.125W, 1/8W; Temperature Coefficient: 100ppm/C; Tolerance: 1%
RT217 RT218 = R: RES SMD 2.7M OHM 5% 1/10W 0603; CLASS: DISCRETE; Company Part Status: New; Manufacturer: Yageo; Manufacturer PN: RC0603JR-072M7L; PART_NUMBER: TMP-1537; Package Size: 0603 (1608 Metric); Rated Power: 0.1W, 1/10W; Temperature Coefficient: 100ppm/C; Tolerance: 5%
RT220 = RES: RES 0.005 OHM 1% 2W 2512; CLASS: DISCRETE; Company Part Status: Released; Manufacturer: Rohm Semiconductor; Manufacturer PN: PMR100HZPFU5L00; PART_NUMBER: TMP-1455; Package Size: 2512 (6432 Metric); Rated Power: 2W; Temperature Coefficient: 100ppm/C; Tolerance: 1%
RT221 = R: RES SMD 200K OHM 1% 1/10W 0603; CLASS: DISCRETE; Company Part Status: New; Manufacturer: Panasonic Electronic Components; Manufacturer PN: ERJ-3EKF2003V; PART_NUMBER: TMP-1536; Package Size: 0603 (1608 Metric); Rated Power: 0.1W, 1/10W; Temperature Coefficient: 100ppm/C; Tolerance: 1%
RT222 = R: RES SMD 22K OHM 1% 1/10W 0603; CLASS: DISCRETE; Manufacturer: Panasonic Electronic Components; Manufacturer PN: ERJ-3EKF2202V; PART_NUMBER: TMP-786; Package Size: 0603 (1608 Metric); Rated Power: 0.1W, 1/10W; Temperature Coefficient: 100ppm/C; Tolerance: 1%
UT22 = LT3581: IC REG MULTI CONFG ADJ 16MSOP; CLASS: IC; Company Part Status: New; Manufacturer: Linear Technology/Analog Devices; Manufacturer PN: LT3581EMSE#PBF; PART_NUMBER: TMP-1596; Package Size: 16-TFSOP (0.118", 3.00mm Width) Exposed Pad
UT24 = MOSFET_N_GSD: MOSFET N-CH 50V 0.2A SOT-23; CLASS: DISCRETE; Company Part Status: Released; Manufacturer: ON Semiconductor; PART_NUMBER: TMP-1374; Package Size: TO-236-3, SC-59, SOT-23-3; Polarity: N-Channel; Rated Power: 350mW
UT33 = LM7805: DC DC CONVERTER 3.3V 5W; CLASS: IC; Company Part Status: New; Manufacturer: Murata Power Solutions Inc.; Manufacturer PN: OKI-78SR-3.3/1.5-W36H-C; PART_NUMBER: TMP-1727; Package Size: 3-SIP Module; Rated Power: 5W; Supply Voltage: 7 - 36 V
UT36 = LM7805: DC DC CONVERTER 5V 8W; CLASS: IC; Company Part Status: New; Manufacturer: Murata Power Solutions Inc.; Manufacturer PN: OKI-78SR-5/1.5-W36H-C; PART_NUMBER: TMP-1728; Package Size: 3-SIP Module; Rated Power: 8W; Supply Voltage: 7 - 36 V
UT37 = LTC4368: IC SURGE SUPPRESSION ADJ 10MSOP; CLASS: IC; Company Part Status: New; Manufacturer: Linear Technology/Analog Devices; PART_NUMBER: TMP-1529; Package Size: 10-MSOP (0.118", 3.00mm Width); Supply Voltage: 2.5 - 60 V
CT91 CT99 CT106 CT116 CT118 CT131 = CAP: CAP CER 1000PF 50V C0G/NP0 0603; CLASS: DISCRETE; Company Part Status: New; Dielectric Type: Capacitors; Manufacturer: Murata Electronics North America; Manufacturer PN: GRM1885C1H102FA01J; PART_NUMBER: TMP-1524; Package Size: 0603 (1608 Metric); Rated Voltage: 50V; Temperature Coefficient: C0G, NP0; Tolerance: 1%
JT41 = HDR_2X5_M: CONN HEADER 2.54MM 10POS GOLD; CLASS: IO; Company Part Status: New; Manufacturer: Sullins Connector Solutions; PART_NUMBER: TMP-399
UB22 = 74LVC8T245: IC TRNSLTR BIDIRECTIONAL 24TSSOP; CLASS: IC; Company Part Status: New; Manufacturer: Nexperia USA Inc.; Manufacturer PN: 74LVC8T245PW,118; PART_NUMBER: TMP-1670; Package Size: 24-TSSOP (0.173", 4.40mm Width); Supply Voltage: 1.2 - 5.5 V

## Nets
+3V3: CB70.1 CB72.1 CT2.1 CT7.1 CT16.1 CT31.1 CT108.1 CT125.1 CT126.1 CT130.1 CT145.1 RB2.1 RB3.1 RB6.1 RB13.1 RB91.1 RB95.1 RB110.1 RB111.1 RT192.1 UB21.3(EN) UB21.4(VIN) UB22.1(VCCA) UT1.16(VCC) UT2.16(VCC) UT4.16(VCC) UT8.16(VCC) UT25.16(VCC) UT26.16(VCC) UT33.3(Output) UT34.16(VCC) UT35.16(VCC) ; also on sheet 1 2 4 5 6 13 14 15 16
+3VREF_B: CB71.1 RB92.1 RB93.1 RB94.1 UB21.5(VREF)
+5V: CB44.1 CB45.1 CB73.1 CT121.1 CT122.1 CT123.1 CT128.1 CT129.1 CT146.1 JB5.2 JT41.4(PIN4) JT41.9(PIN9) RT148.1 RT156.1 RT166.1 RT172.1 RT186.1 RT193.1 RT194.1 UB18.20(VCC) UB19.20(VCC) UB22.24(VCCB) UT27.20(VCC) UT28.20(VCC) UT29.4(VCC) UT30.4(VCC) UT31.4(VCC) UT36.3(Output) ; also on sheet 4 5 6
+12V: CT90.1 CT111.1 CT134.1 CT147.1 DT2.A(ANODE) JB2.1 JB3.1 JB4.1 JB6.1 JB7.1 JB8.1 LT13.1 RT145.1 RT146.2 RT220.2 UT22.5(VIN) UT33.1(Input) UT36.1(Input) UT37.8(VOUT) ; also on sheet 5
+15V: CT87.1 QT1.5(D) ; also on sheet 1 2
VIN: JT42.1 QT3.5(D) RT217.1 RT223.1 UT37.1(VIN)
0: CB44.2 CB45.2 CB58.2 CB59.2 CB60.2 CB69.2 CB70.2 CB71.2 CB72.2 CB73.2 CB74.1 CB75.1 CB76.1 CT1.2 CT2.2 CT3.2 CT4.2 CT5.2 CT6.2 CT7.2 CT14.2 CT16.2 CT31.2 CT87.2 CT88.2 CT90.2 CT91.2 CT97.1 CT98.1 CT99.2 CT100.2 CT104.2 CT106.2 CT107.2 CT108.2 CT109.2 CT110.2 CT111.2 CT116.2 CT118.2 CT120.2 CT121.2 CT122.2 CT123.2 CT124.2 CT125.2 CT126.2 CT127.2 CT128.2 CT129.2 CT130.2 CT131.2 CT134.2 CT136.1 CT137.2 CT138.1 CT139.2 CT140.1 CT141.2 CT145.2 CT146.2 CT147.2 CT148.2 CT149.2 DT7.2(C) DT8.2(C) JB2.2 JB2.12 JB2.14 JB2.16 JB3.2 JB3.12 JB3.14 JB3.16 JB4.2 JB4.12 JB4.14 JB4.16 JB5.1 JB5.S1(SHIELD) JB6.2 JB6.12 JB6.14 JB6.16 JB7.2 JB7.12 JB7.14 JB7.16 JB8.2 JB8.12 JB8.14 JB8.16 JT41.5(PIN5) JT41.10(PIN10) JT42.2 JT42.3 RB1.1 RB4.1 RB5.2 RB14.2 RB90.1 RB96.1 RB98.2 RB100.2 RB102.2 RB109.2 RB112.2 RT144.1 RT147.2 RT160.2 RT221.2 UB18.1(OE1) UB18.2(A1) UB18.3(A2) UB18.10(GND) UB18.19(OE2) UB19.1(OE1) UB19.5(A4) UB19.6(A5) UB19.7(A6) UB19.8(A7) UB19.9(A8) UB19.10(GND) UB19.19(OE2) UB21.2(GND) UB22.2(DIR) UB22.11(GND) UB22.14(B7) UB22.15(B6) UB22.22(~{OE}) UT1.8(GND) UT2.8(GND) UT4.8(GND) UT8.8(GND) UT22.16(SYNC) UT22.17(GND) UT24.2(S) UT25.8(GND) UT26.8(GND) UT27.1(OE1) UT27.2(A1) UT27.3(A2) UT27.10(GND) UT27.19(OE2) UT28.1(OE1) UT28.5(A4) UT28.6(A5) UT28.7(A6) UT28.8(A7) UT28.9(A8) UT28.10(GND) UT28.19(OE2) UT29.2(IN1-) UT29.3(IN1+) UT29.11(GND) UT30.2(IN1-) UT30.3(IN1+) UT30.11(GND) UT31.2(IN1-) UT31.3(IN1+) UT31.11(GND) UT33.2(Gnd) UT34.8(GND) UT35.8(GND) UT36.2(Gnd) UT37.5(GND) ; also on sheet 1 2 3 4 5 6 13 14 15 16
Current-X: CB60.1 RT171.2 ; also on sheet 3 5
Current-X_N: JB5.7 RT210.1 RT213.2
Current-X_P: JB5.8 RT209.1 RT213.1
Current-Y: CB59.1 RT170.2 ; also on sheet 3 5
Current-Y_N: JB5.5 RT208.1 RT212.2
Current-Y_P: JB5.4 RT207.1 RT212.1
Current-Z: CB58.1 RT169.2 ; also on sheet 3 5
Current-Z_N: JB5.3 RT206.1 RT211.2
Current-Z_P: JB5.6 RT205.1 RT211.1
QEA_A: UB22.3(A0) ; also on sheet 5
QEA_B: UB22.4(A1) ; also on sheet 5
QEA_I: UB22.5(A2) ; also on sheet 5
QEB_A: UB22.6(A3) ; also on sheet 5
QEB_B: UB22.7(A4) ; also on sheet 5
QEB_I: UB22.8(A5) ; also on sheet 5
QEPA-A-IN: CT118.1 JT41.1(PIN1) RT186.2 UB22.21(B0)
QEPA-B-IN: CT131.1 JT41.2(PIN2) RT194.2 UB22.20(B1)
QEPA-I-IN: CT116.1 JT41.3(PIN3) RT172.2 UB22.19(B2)
QEPB-A-IN: CT106.1 JT41.6(PIN6) RT166.2 UB22.18(B3)
QEPB-B-IN: CT99.1 JT41.7(PIN7) RT156.2 UB22.17(B4)
QEPB-I-IN: CT91.1 JT41.8(PIN8) RT148.2 UB22.16(B5)
Shutdown+15V: RT160.1 RT161.1 ; also on sheet 5
U-FAULT: UT8.3(Y1) ; also on sheet 5
U-FAULT-N: JB4.8 LT12.1
U-FAULT-N-Filter: CT27.2 LT12.2 RT49.2 UT8.1(B1)
U-FAULT-P: JB4.7 LT9.1
U-FAULT-P-Filter: CT27.1 LT9.2 RT49.1 UT8.2(A1)
U-LEN: JB4.13 UB18.12(Y7)
U-LEN-OUT: UB18.8(A7) ; also on sheet 5
U-OCEN: JB4.15 UB18.11(Y8)
U-OCEN-OUT: UB18.9(A8) ; also on sheet 5
U-PSDIS: JB4.11 UB18.13(Y6)
U-PSDIS-OUT: UB18.7(A6) ; also on sheet 5
U-RTD: UT8.5(Y2) ; also on sheet 5 13
U-RTD-N: JB4.10 LT3.1
U-RTD-N-Filter: CT20.2 LT3.2 RT32.2 UT8.7(B2)
U-RTD-P: JB4.9 LT6.1
U-RTD-P-Filter: CT20.1 LT6.2 RT32.1 UT8.6(A2)
UHS-PWM: RT20.1 ; also on sheet 3 5
UHS-PWM-N: JB4.4 UT1.3(Z1)
UHS-PWM-P: JB4.3 UT1.2(Y1)
ULS-PWM: RT3.1 ; also on sheet 3 5
ULS-PWM-N: JB4.6 UT1.5(Z2)
ULS-PWM-P: JB4.5 UT1.6(Y2)
V-FAULT: UT8.11(Y3) ; also on sheet 5
V-FAULT-N: JB3.8 LT1.1
V-FAULT-N-Filter: CT18.2 LT1.2 RT30.2 UT8.9(B3)
V-FAULT-P: JB3.7 LT4.1
V-FAULT-P-Filter: CT18.1 LT4.2 RT30.1 UT8.10(A3)
V-LEN: JB3.13 UB18.15(Y4)
V-LEN-OUT: UB18.5(A4) ; also on sheet 5
V-OCEN: JB3.15 UB18.14(Y5)
V-OCEN-OUT: UB18.6(A5) ; also on sheet 5
V-PSDIS: JB3.11 UB18.16(Y3)
V-PSDIS-OUT: UB18.4(A3) ; also on sheet 5
V-RTD: UT8.13(Y4) ; also on sheet 5 13
V-RTD-N: JB3.10 LT11.1
V-RTD-N-Filter: CT26.2 LT11.2 RT48.2 UT8.15(B4)
V-RTD-P: JB3.9 LT8.1
V-RTD-P-Filter: CT26.1 LT8.2 RT48.1 UT8.14(A4)
VHS-PWM: RT2.1 ; also on sheet 3 5
VHS-PWM-N: JB3.4 UT1.11(Z3)
VHS-PWM-P: JB3.3 UT1.10(Y3)
VLS-PWM: RT13.1 ; also on sheet 3 5
VLS-PWM-N: JB3.6 UT1.13(Z4)
VLS-PWM-P: JB3.5 UT1.14(Y4)
W-FAULT: UT4.3(Y1) ; also on sheet 5
W-FAULT-N: JB2.8 LT2.1
W-FAULT-N-Filter: CT19.2 LT2.2 RT31.2 UT4.1(B1)
W-FAULT-P: JB2.7 LT5.1
W-FAULT-P-Filter: CT19.1 LT5.2 RT31.1 UT4.2(A1)
W-LEN: JB2.13 UB19.17(Y2)
W-LEN-OUT: UB19.3(A2) ; also on sheet 5
W-OCEN: JB2.15 UB19.16(Y3)
W-OCEN-OUT: UB19.4(A3) ; also on sheet 5
W-PSDIS: JB2.11 UB19.18(Y1)
W-PSDIS-OUT: UB19.2(A1) ; also on sheet 5
W-RTD: UT4.5(Y2) ; also on sheet 5 13
W-RTD-N: JB2.10 LT10.1
W-RTD-N-Filter: CT25.2 LT10.2 RT47.2 UT4.7(B2)
W-RTD-P: JB2.9 LT7.1
W-RTD-P-Filter: CT25.1 LT7.2 RT47.1 UT4.6(A2)
WHS-PWM: RT1.1 ; also on sheet 3 5
WHS-PWM-N: JB2.4 UT2.3(Z1)
WHS-PWM-P: JB2.3 UT2.2(Y1)
WLS-PWM: RT28.1 ; also on sheet 3 5
WLS-PWM-N: JB2.6 UT2.5(Z2)
WLS-PWM-P: JB2.5 UT2.6(Y2)
X-FAULT: UT35.3(Y1) ; also on sheet 5
X-FAULT-N: JB8.8 LT25.1
X-FAULT-N-Filter: CT144.2 LT25.2 RT216.2 UT35.1(B1)
X-FAULT-P: JB8.7 LT22.1
X-FAULT-P-Filter: CT144.1 LT22.2 RT216.1 UT35.2(A1)
X-LEN: JB8.13 UT27.12(Y7)
X-LEN-OUT: UT27.8(A7) ; also on sheet 5
X-OCEN: JB8.15 UT27.11(Y8)
X-OCEN-OUT: UT27.9(A8) ; also on sheet 5
X-PSDIS: JB8.11 UT27.13(Y6)
X-PSDIS-OUT: UT27.7(A6) ; also on sheet 5
X-RTD: UT35.5(Y2) ; also on sheet 5 13
X-RTD-N: JB8.10 LT16.1
X-RTD-N-Filter: CT135.2 LT16.2 RT204.2 UT35.7(B2)
X-RTD-P: JB8.9 LT19.1
X-RTD-P-Filter: CT135.1 LT19.2 RT204.1 UT35.6(A2)
XHS-PWM: RT190.1 ; also on sheet 3 5
XHS-PWM-N: JB8.4 UT25.3(Z1)
XHS-PWM-P: JB8.3 UT25.2(Y1)
XLS-PWM: RT168.1 ; also on sheet 3 5
XLS-PWM-N: JB8.6 UT25.5(Z2)
XLS-PWM-P: JB8.5 UT25.6(Y2)
Y-FAULT: UT35.11(Y3) ; also on sheet 5
Y-FAULT-N: JB7.8 LT14.1
Y-FAULT-N-Filter: CT132.2 LT14.2 RT196.2 UT35.9(B3)
Y-FAULT-P: JB7.7 LT17.1
Y-FAULT-P-Filter: CT132.1 LT17.2 RT196.1 UT35.10(A3)
Y-LEN: JB7.13 UT27.15(Y4)
Y-LEN-OUT: UT27.5(A4) ; also on sheet 5
Y-OCEN: JB7.15 UT27.14(Y5)
Y-OCEN-OUT: UT27.6(A5) ; also on sheet 5
Y-PSDIS: JB7.11 UT27.16(Y3)
Y-PSDIS-OUT: UT27.4(A3) ; also on sheet 5
Y-RTD: UT35.13(Y4) ; also on sheet 5 13
Y-RTD-N: JB7.10 LT24.1
Y-RTD-N-Filter: CT143.2 LT24.2 RT215.2 UT35.15(B4)
Y-RTD-P: JB7.9 LT21.1
Y-RTD-P-Filter: CT143.1 LT21.2 RT215.1 UT35.14(A4)
YHS-PWM: RT167.1 ; also on sheet 3 5
YHS-PWM-N: JB7.4 UT25.11(Z3)
YHS-PWM-P: JB7.3 UT25.10(Y3)
YLS-PWM: RT185.1 ; also on sheet 3 5
YLS-PWM-N: JB7.6 UT25.13(Z4)
YLS-PWM-P: JB7.5 UT25.14(Y4)
Z-FAULT: UT34.3(Y1) ; also on sheet 5
Z-FAULT-N: JB6.8 LT15.1
Z-FAULT-N-Filter: CT133.2 LT15.2 RT197.2 UT34.1(B1)
Z-FAULT-P: JB6.7 LT18.1
Z-FAULT-P-Filter: CT133.1 LT18.2 RT197.1 UT34.2(A1)
Z-LEN: JB6.13 UT28.17(Y2)
Z-LEN-OUT: UT28.3(A2) ; also on sheet 5
Z-OCEN: JB6.15 UT28.16(Y3)
Z-OCEN-OUT: UT28.4(A3) ; also on sheet 5
Z-PSDIS: JB6.11 UT28.18(Y1)
Z-PSDIS-OUT: UT28.2(A1) ; also on sheet 5
Z-RTD: UT34.5(Y2) ; also on sheet 5 13
Z-RTD-N: JB6.10 LT23.1
Z-RTD-N-Filter: CT142.2 LT23.2 RT214.2 UT34.7(B2)
Z-RTD-P: JB6.9 LT20.1
Z-RTD-P-Filter: CT142.1 LT20.2 RT214.1 UT34.6(A2)
ZHS-PWM: RT165.1 ; also on sheet 3 5
ZHS-PWM-N: JB6.4 UT26.3(Z1)
ZHS-PWM-P: JB6.3 UT26.2(Y1)
ZLS-PWM: RT195.1 ; also on sheet 3 5
ZLS-PWM-N: JB6.6 UT26.5(Z2)
ZLS-PWM-P: JB6.5 UT26.6(Y2)
N07282: RB13.2 UT8.4(G)
N07299: RB5.1 UT8.12(~{G})
N07508: RB6.2 UT4.4(G)
N07516: RB14.1 UT4.12(~{G})
N07693: RB3.2 UT1.4(EN)
N07878: RB2.2 UT2.4(EN)
N09835: CT6.1 RT20.2 UT1.1(A1)
N10049: CT4.1 RT3.2 UT1.7(A2)
N10085: CT3.1 RT2.2 UT1.9(A3)
N10121: CT5.1 RT13.2 UT1.15(A4)
N11382: RB1.2 UT1.12(~{EN})
N11987: RB4.2 UT2.12(~{EN})
N12714: CT1.1 RT1.2 UT2.1(A1)
N12754: CT14.1 RT28.2 UT2.7(A2)
N88263: DT7.1(A) RT192.2
N88433: DT8.1(A) RT193.2
N147166: QT2.1(S) QT3.1(S)
N148075: QT2.4(G) QT3.4(G) RT222.2 UT37.10(GATE)
N148197: CT149.1 RT222.1
N148540: QT2.5(D) RT220.1 UT37.9(SENSE)
N149103: RT217.2 RT218.1 UT37.6(/SHDN)
N149107: RT218.2 RT219.1 UT37.2(UV)
N149113: RT219.2 RT221.1 UT37.3(OV)
N149983: CT148.1 UT37.4(RETRY)
N150621: RT223.2 UT37.7(/FAULT)
N353091: RB111.2 UT35.4(G)
N353097: RB109.1 UT35.12(~{G})
N353101: RB110.2 UT34.4(G)
N353105: RB112.1 UT34.12(~{G})
N353111: RB95.2 UT25.4(EN)
N353117: RB91.2 UT26.4(EN)
N353179: CT124.1 RT190.2 UT25.1(A1)
N353185: CT110.1 RT168.2 UT25.7(A2)
N353187: CT109.1 RT167.2 UT25.9(A3)
N353189: CT120.1 RT185.2 UT25.15(A4)
N353203: RB90.2 UT25.12(~{EN})
N353215: RB96.2 UT26.12(~{EN})
N353221: CT107.1 RT165.2 UT26.1(A1)
N353229: CT127.1 RT195.2 UT26.7(A2)
N4895784: CT137.1 RT199.1 RT206.2
N4895786: CT136.2 RT198.1 RT205.2
N4895800: RT198.2 UT29.5(IN2+)
N4895802: RB97.1 UT29.6(IN2-) UT29.7(OUT2)
N4895808: RT199.2 UT29.10(IN3+)
N4895810: RT187.1 UT29.8(OUT3) UT29.9(IN3-)
N4895816: CT113.1 RT181.1 RT187.2 UT29.13(IN4-)
N4895820: CT113.2 RT169.1 RT181.2 UT29.14(OUT4)
N4895842: CB74.2 RB92.2 RB97.2 RB98.1 UT29.12(IN4+)
N4895902: CB75.2 RB93.2 RB99.2 RB100.1 UT30.12(IN4+)
N4895932: CT138.2 RT200.1 RT207.2
N4895942: RT200.2 UT30.5(IN2+)
N4895944: RB99.1 UT30.6(IN2-) UT30.7(OUT2)
N4895958: CT114.2 RT170.1 RT182.2 UT30.14(OUT4)
N4895962: CT114.1 RT182.1 RT188.2 UT30.13(IN4-)
N4895972: CT139.1 RT201.1 RT208.2
N4895978: RT201.2 UT30.10(IN3+)
N4895980: RT188.1 UT30.8(OUT3) UT30.9(IN3-)
N4896016: CB76.2 RB94.2 RB101.2 RB102.1 UT31.12(IN4+)
N4896046: CT140.2 RT202.1 RT209.2
N4896056: RT202.2 UT31.5(IN2+)
N4896058: RB101.1 UT31.6(IN2-) UT31.7(OUT2)
N4896072: CT115.2 RT171.1 RT183.2 UT31.14(OUT4)
N4896076: CT115.1 RT183.1 RT189.2 UT31.13(IN4-)
N4896086: CT141.1 RT203.1 RT210.2
N4896092: RT203.2 UT31.10(IN3+)
N4896094: RT189.1 UT31.8(OUT3) UT31.9(IN3-)
N5226417: CB69.1 UB21.1(VREF/2)
N5307958: DT3.2(A) LT13.2 UT22.6(SW1) UT22.9(SW2)
N5307974: CT88.1 DT3.1(C) QT1.1(S) RT124.1 RT159.2
N5308194: DT2.C(CATHODE) QT1.4(G) RT124.2 UT22.3(GATE)
N5308444: RT159.1 UT22.1(FB)
N5308460: RT146.1 RT147.1 UT22.13(~SHDN) UT24.3(D)
N5308524: RT145.2 UT22.4(~FAULT)
N5308650: RT144.2 UT22.14(RT)
N5308658: CT98.2 RT155.1 UT22.2(Vc)
N5308734: CT97.2 UT22.15(SS)
N5308830: CT104.1 RT155.2
N5309781: CT100.1 RT161.2 UT24.1(G)

Not connected (* = marked no-connect by the designer): JB5 S2(SHIELD2); QT1 2(S1) 3(S2) 6(D1) 7(D2) 8(D3); QT2 2(S1) 3(S2) 6(D1) 7(D2) 8(D3); QT3 2(S1) 3(S2) 6(D1) 7(D2) 8(D3); UB18 17(Y2) 18(Y1); UB19 11(Y8) 12(Y7) 13(Y6) 14(Y5) 15(Y4); UB22 9(A6) 10(A7) 12(GND1) 13(GND2) 23(VCCB1); UT2 9(A3) 10(Y3) 11(Z3) 13(Z4) 14(Y4) 15(A4); UT4 9(B3) 10(A3) 11(Y3) 13(Y4) 14(A4) 15(B4); UT22 7(SW11) 8(SW12) 10(SW21) 11(SW22) 12(CLKOUT); UT26 9(A3) 10(Y3) 11(Z3) 13(Z4) 14(Y4) 15(A4); UT27 17(Y2) 18(Y1); UT28 11(Y8) 12(Y7) 13(Y6) 14(Y5) 15(Y4); UT29 1(OUT1); UT30 1(OUT1); UT31 1(OUT1); UT34 9(B3) 10(A3) 11(Y3) 13(Y4) 14(A4) 15(B4)

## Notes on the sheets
sheet 7
- 3V Bias for Current Sensors XYZ
sheet 8
- 296-18698-1-ND
sheet 9
- 296-18698-1-ND
sheet 10
- DC INPUT
- Power Supply:
  PSAC60M-120 993-1107-ND
  PSAA30R-120 993-1118-ND
- Plug: CP3-1000-ND
- 2V @5mA
  0805 Green
sheet 12
- Revision History:
- V1.0: 5/7/2020
  -Initial Release
- V1.1B: 8/20/2020
  -Corrected ControlCard pinout mismatch
  -ADM3057 CAN transceiver + power
  -Cleaned silkscreen text
  V1.1B: 10/16/2020
  -Corrected resolver circuit wiring in OPA2209
  -Changed RT220 to 5mOhm, set limit to 10A for increased inrush current
  V1.2A: 12/30/2020
  -Changed resolver circuit to ALM2402
  V1.2B 7/15/2021
  -Changed filter capacitors and gain in resolver excitation circuit
  -Changed filter capacitors in current sensor receiver circuit
